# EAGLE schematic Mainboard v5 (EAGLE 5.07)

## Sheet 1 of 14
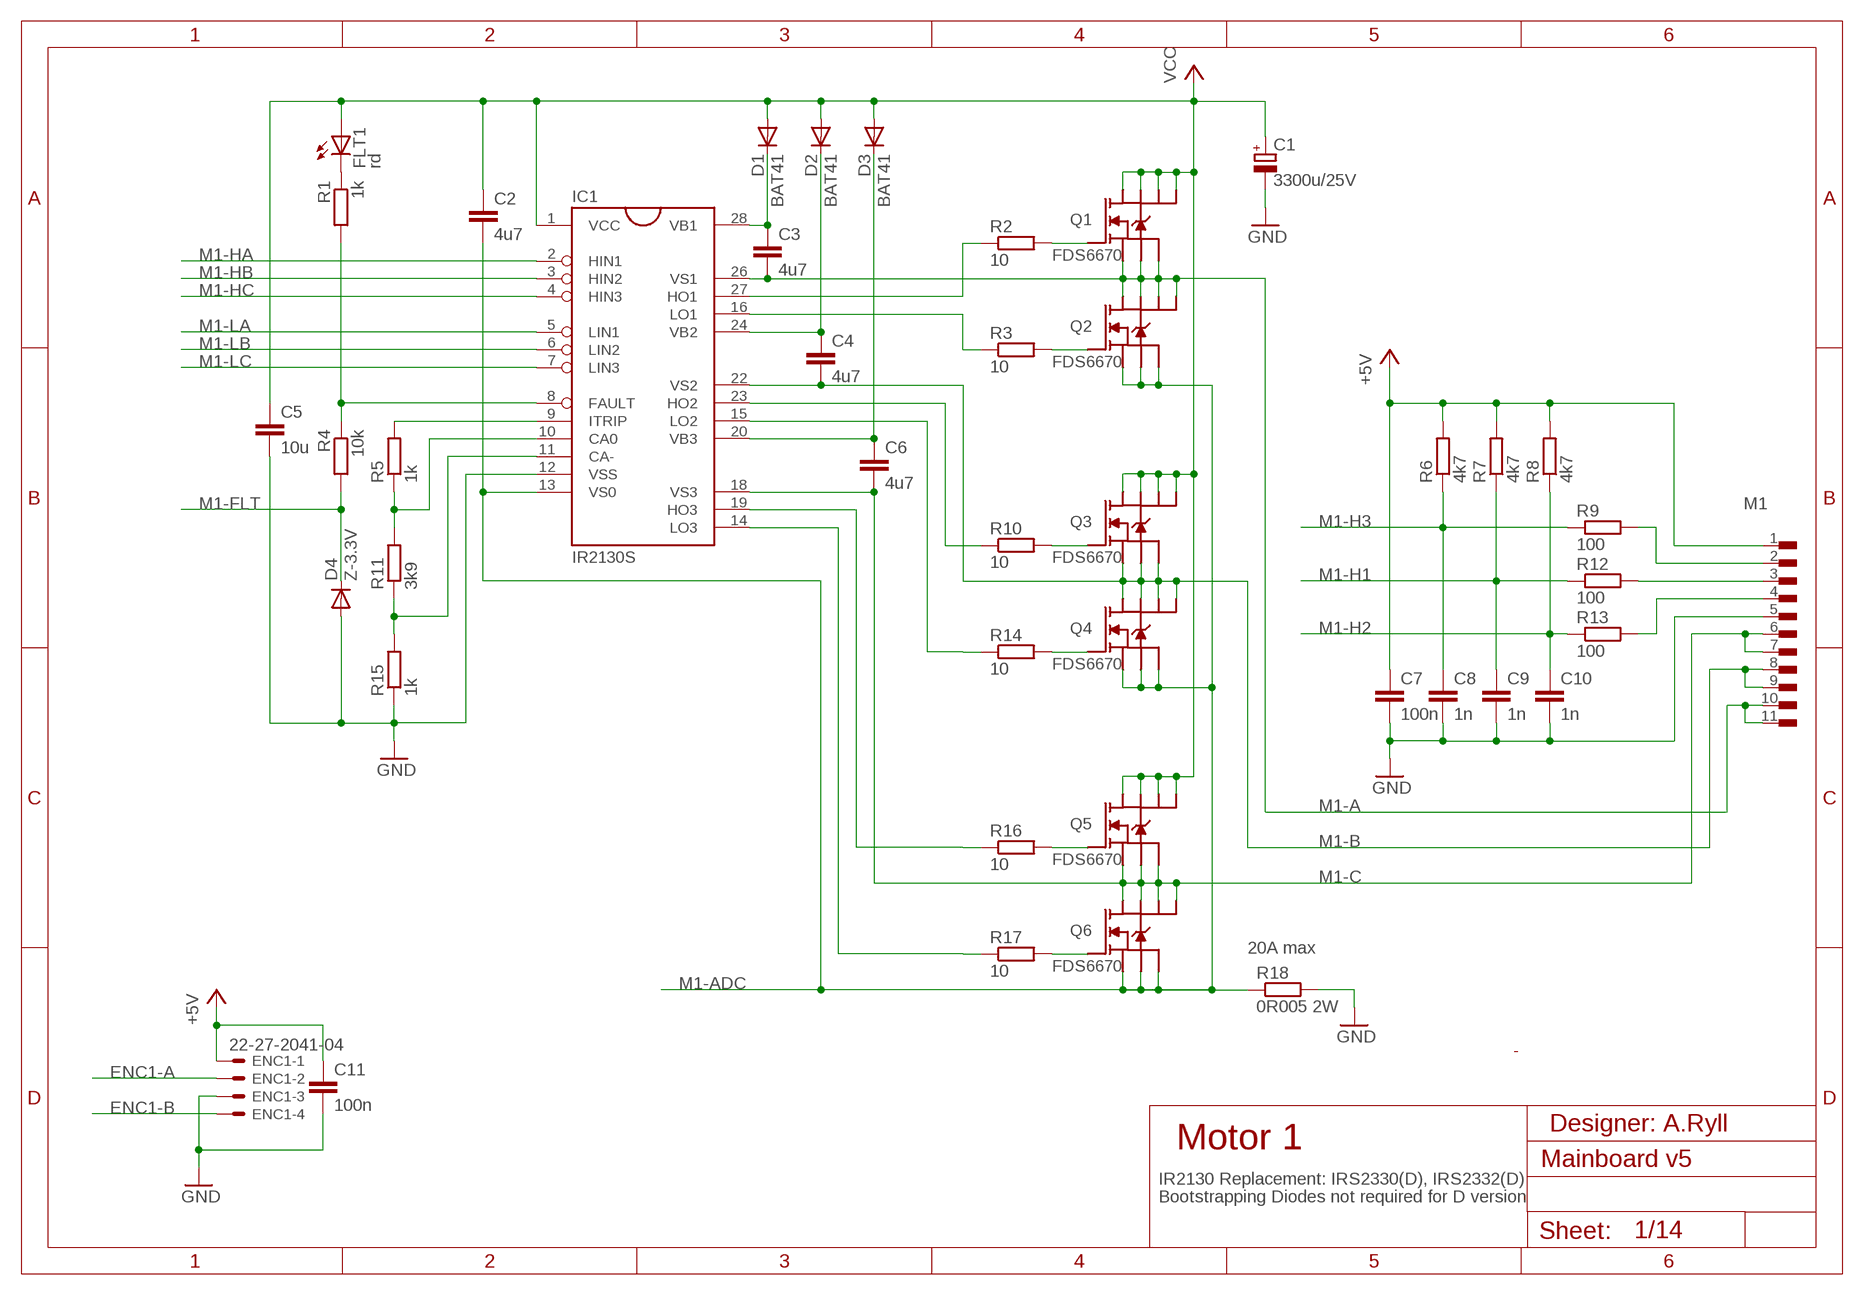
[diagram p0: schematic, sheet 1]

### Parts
C1  3300u/25V  CPOL-EU  [C25-16L]
C2  4u7  C-EUC0805  [C0805]
C3  4u7  C-EUC0805  [C0805]
C4  4u7  C-EUC0805  [C0805]
C5  10u  C-EUC0805  [C0805]
C6  4u7  C-EUC0805  [C0805]
C7  100n  C-EUC0805  [C0805]
C8  1n  C-EUC0805  [C0805]
C9  1n  C-EUC0805  [C0805]
C10  1n  C-EUC0805  [C0805]
C11  100n  C-EUC0805  [C0805]
D1  BAT41  DIODE-SOD323-W  [SOD323-W]
D2  BAT41  DIODE-SOD323-W  [SOD323-W]
D3  BAT41  DIODE-SOD323-W  [SOD323-W]
D4  Z-3.3V  DIODE-SOD323-W  [SOD323-W]
ENC1  22-27-2041-04  [6410-04]
FLT1  rd  LEDCHIP-LED0805  [CHIP-LED0805]
IC1  IR2130S  [SO28W]
M1  MOLEX11  [MOLEX11]
Q1  FDS6670  NMOS4D  [SOIC8]
Q2  FDS6670  NMOS4D  [SOIC8]
Q3  FDS6670  NMOS4D  [SOIC8]
Q4  FDS6670  NMOS4D  [SOIC8]
Q5  FDS6670  NMOS4D  [SOIC8]
Q6  FDS6670  NMOS4D  [SOIC8]
R1  1k  R-EU_R0805  [R0805]
R2  10  R-EU_R0805  [R0805]
R3  10  R-EU_R0805  [R0805]
R4  10k  R-EU_R0805  [R0805]
R5  1k  R-EU_R0805  [R0805]
R6  4k7  R-EU_R0805  [R0805]
R7  4k7  R-EU_R0805  [R0805]
R8  4k7  R-EU_R0805  [R0805]
R9  100  R-EU_R0805  [R0805]
R10  10  R-EU_R0805  [R0805]
R11  3k9  R-EU_R0805  [R0805]
R12  100  R-EU_R0805  [R0805]
R13  100  R-EU_R0805  [R0805]
R14  10  R-EU_R0805  [R0805]
R15  1k  R-EU_R0805  [R0805]
R16  10  R-EU_R0805  [R0805]
R17  10  R-EU_R0805  [R0805]
R18  0R005 2W  R-EU_R2512  [R2512]

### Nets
+5V: C7.1 C11.1 ENC1.1 M1.1(-1) R6.2 R7.2 R8.2 ; also sheet 2,3,4,5,8,12
ENC1-A: ENC1.2 ; also sheet 11
ENC1-B: ENC1.4 ; also sheet 11
FLT1: IC1.8(FAULT) R1.2 R4.1
GND: C1.B(-) C5.2 C7.2 C8.2 C9.2 C10.2 C11.2 D4.A ENC1.3 IC1.12(VSS) M1.5(-5) R15.1 R18.2 ; also sheet 2,3,4,5,6,7,8,9,10,11,12,13,14
M1-A: C3.2 IC1.26(VS1) M1.10(-10) M1.11(-11) Q1.1(S1) Q1.2(S2) Q1.3(S3) Q2.5(D1) Q2.6(D2) Q2.7(D3) Q2.8(D4)
M1-ADC: C2.2 IC1.13(VS0) Q2.1(S1) Q2.2(S2) Q2.3(S3) Q4.1(S1) Q4.2(S2) Q4.3(S3) Q6.1(S1) Q6.2(S2) Q6.3(S3) R18.1 ; also sheet 6
M1-B: C4.2 IC1.22(VS2) M1.8(-8) M1.9(-9) Q3.1(S1) Q3.2(S2) Q3.3(S3) Q4.5(D1) Q4.6(D2) Q4.7(D3) Q4.8(D4)
M1-C: C6.2 IC1.18(VS3) M1.6(-6) M1.7(-7) Q5.1(S1) Q5.2(S2) Q5.3(S3) Q6.5(D1) Q6.6(D2) Q6.7(D3) Q6.8(D4)
M1-FLT: D4.C R4.2 ; also sheet 7
M1-H1: C9.1 R7.1 R12.1 ; also sheet 8,11
M1-H2: C10.1 R8.1 R13.1 ; also sheet 8,11
M1-H3: C8.1 R6.1 R9.1 ; also sheet 8,11
M1-HA: IC1.2(HIN1) ; also sheet 11
M1-HB: IC1.3(HIN2) ; also sheet 11
M1-HC: IC1.4(HIN3) ; also sheet 11
M1-LA: IC1.5(LIN1) ; also sheet 11
M1-LB: IC1.6(LIN2) ; also sheet 11
M1-LC: IC1.7(LIN3) ; also sheet 11
N$1: IC1.9(ITRIP) R5.2
N$2: Q1.4(G) R2.2
N$3: IC1.27(HO1) R2.1
N$4: Q2.4(G) R3.2
N$5: IC1.23(HO2) R10.1
N$8: M1.2(-2) R9.2
N$9: M1.3(-3) R12.2
N$10: M1.4(-4) R13.2
N$11: Q3.4(G) R10.2
N$12: IC1.15(LO2) R14.1
N$13: Q4.4(G) R14.2
N$16: IC1.19(HO3) R16.1
N$17: Q5.4(G) R16.2
N$18: IC1.14(LO3) R17.1
N$19: Q6.4(G) R17.2
N$33: C3.1 D1.C IC1.28(VB1)
N$35: C4.1 D2.C IC1.24(VB2)
N$37: C6.1 D3.C IC1.20(VB3)
N$39: IC1.16(LO1) R3.1
N$46: IC1.11(CA-) R11.1 R15.2
N$51: FLT1.C R1.1
N$146: IC1.10(CA0) R5.1 R11.2
VCC: C1.A(+) C2.1 C5.1 D1.A D2.A D3.A FLT1.A IC1.1(VCC) Q1.5(D1) Q1.6(D2) Q1.7(D3) Q1.8(D4) Q3.5(D1) Q3.6(D2) Q3.7(D3) Q3.8(D4) Q5.5(D1) Q5.6(D2) Q5.7(D3) Q5.8(D4) ; also sheet 2,3,4,5,12

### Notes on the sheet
- 20A max
- Designer: A.Ryll
- Motor 1
- IR2130 Replacement: IRS2330(D), IRS2332(D)
- Bootstrapping Diodes not required for D version

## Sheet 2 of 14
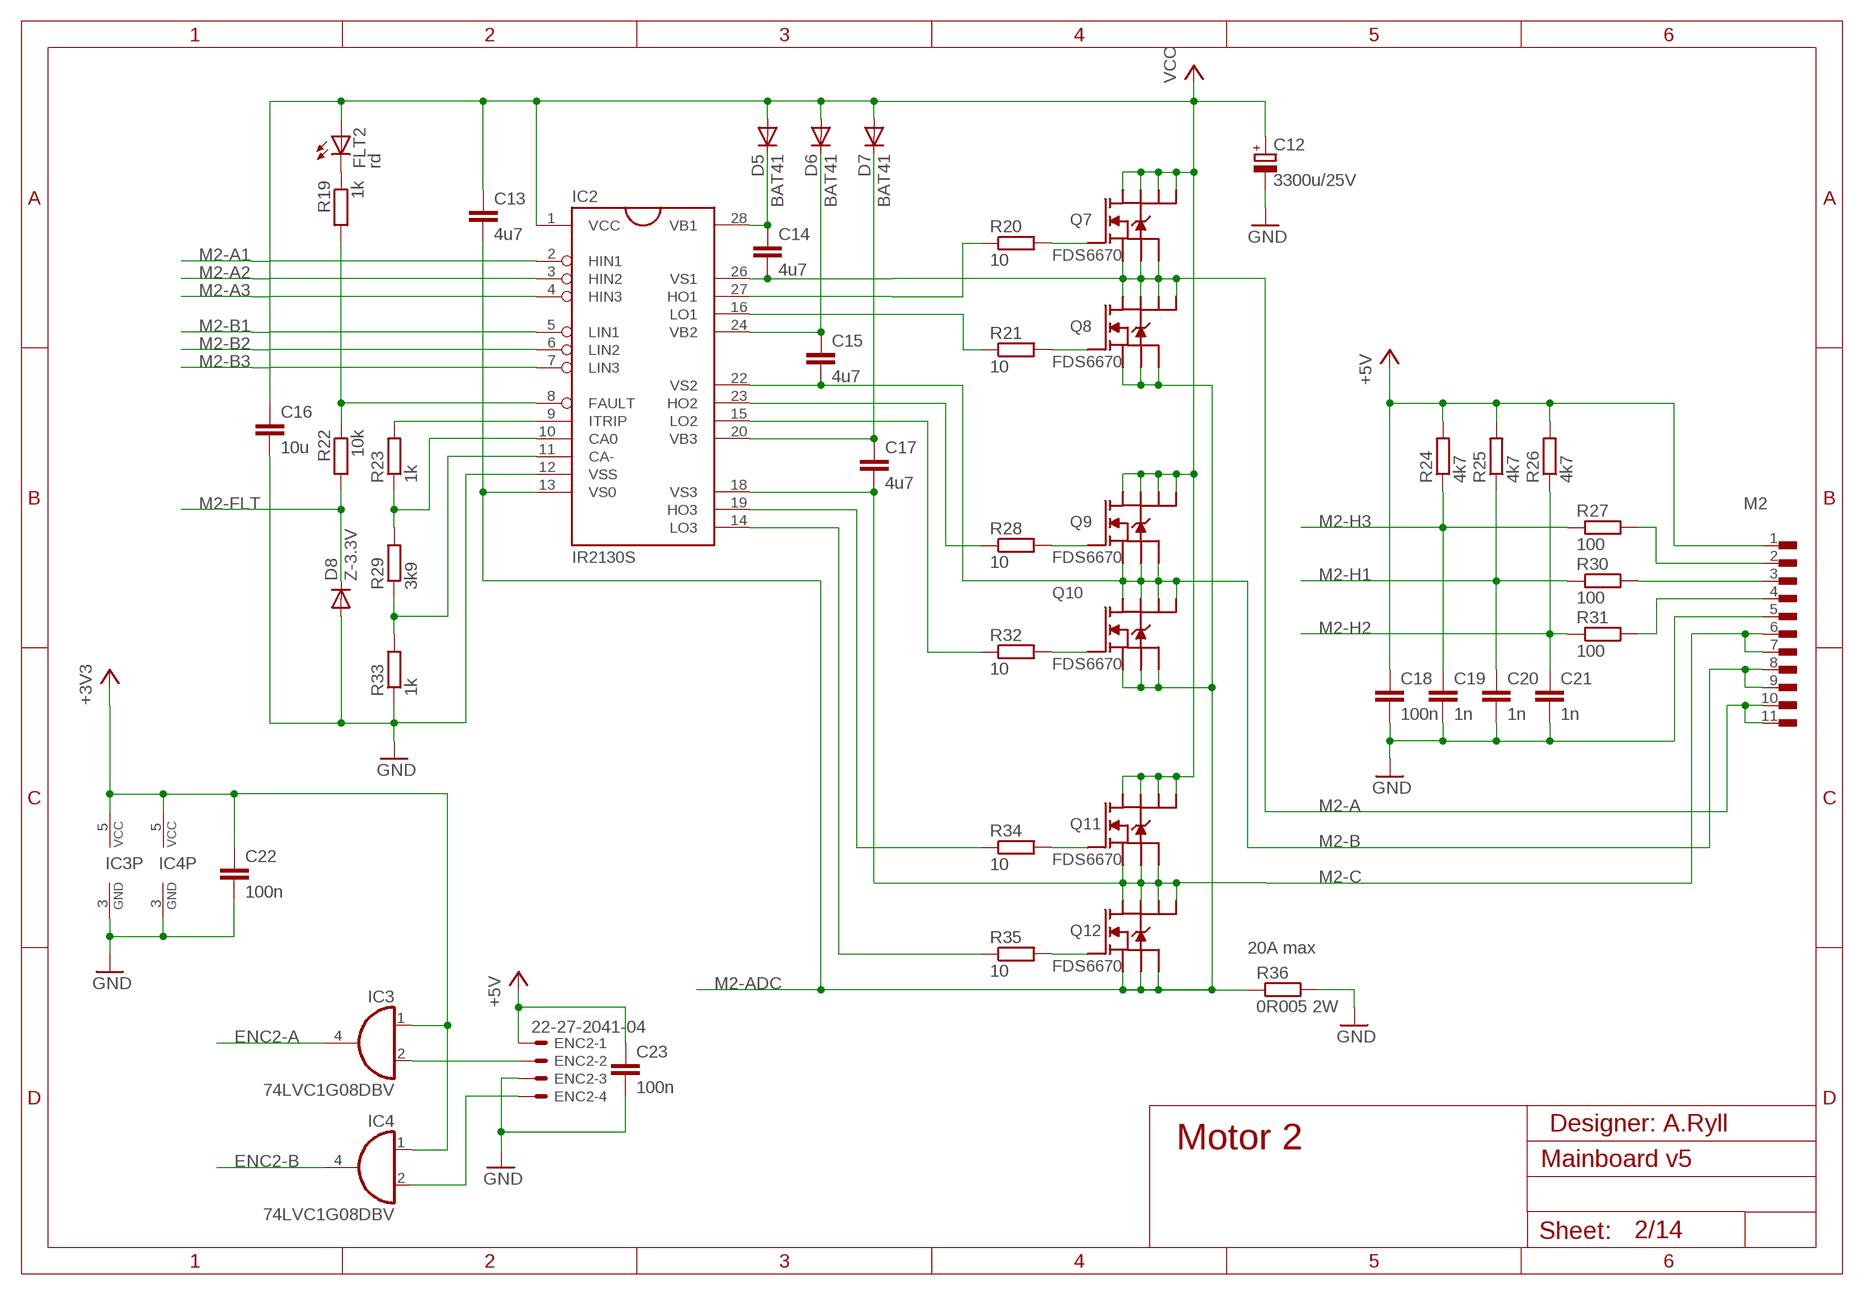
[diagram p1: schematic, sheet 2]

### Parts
C12  3300u/25V  CPOL-EU  [C25-16L]
C13  4u7  C-EUC0805  [C0805]
C14  4u7  C-EUC0805  [C0805]
C15  4u7  C-EUC0805  [C0805]
C16  10u  C-EUC0805  [C0805]
C17  4u7  C-EUC0805  [C0805]
C18  100n  C-EUC0805  [C0805]
C19  1n  C-EUC0805  [C0805]
C20  1n  C-EUC0805  [C0805]
C21  1n  C-EUC0805  [C0805]
C22  100n  C-EUC0805  [C0805]
C23  100n  C-EUC0805  [C0805]
D5  BAT41  DIODE-SOD323-W  [SOD323-W]
D6  BAT41  DIODE-SOD323-W  [SOD323-W]
D7  BAT41  DIODE-SOD323-W  [SOD323-W]
D8  Z-3.3V  DIODE-SOD323-W  [SOD323-W]
ENC2  22-27-2041-04  [6410-04]
FLT2  rd  LEDCHIP-LED0805  [CHIP-LED0805]
IC2  IR2130S  [SO28W]
IC3  74LVC1G08DBV  [SOT23-5]
IC4  74LVC1G08DBV  [SOT23-5]
M2  MOLEX11  [MOLEX11]
Q7  FDS6670  NMOS4D  [SOIC8]
Q8  FDS6670  NMOS4D  [SOIC8]
Q9  FDS6670  NMOS4D  [SOIC8]
Q10  FDS6670  NMOS4D  [SOIC8]
Q11  FDS6670  NMOS4D  [SOIC8]
Q12  FDS6670  NMOS4D  [SOIC8]
R19  1k  R-EU_R0805  [R0805]
R20  10  R-EU_R0805  [R0805]
R21  10  R-EU_R0805  [R0805]
R22  10k  R-EU_R0805  [R0805]
R23  1k  R-EU_R0805  [R0805]
R24  4k7  R-EU_R0805  [R0805]
R25  4k7  R-EU_R0805  [R0805]
R26  4k7  R-EU_R0805  [R0805]
R27  100  R-EU_R0805  [R0805]
R28  10  R-EU_R0805  [R0805]
R29  3k9  R-EU_R0805  [R0805]
R30  100  R-EU_R0805  [R0805]
R31  100  R-EU_R0805  [R0805]
R32  10  R-EU_R0805  [R0805]
R33  1k  R-EU_R0805  [R0805]
R34  10  R-EU_R0805  [R0805]
R35  10  R-EU_R0805  [R0805]
R36  0R005 2W  R-EU_R2512  [R2512]

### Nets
+3V3: C22.1 IC3.1(I0) IC3.5(VCC) IC4.1(I0) IC4.5(VCC) ; also sheet 6,7,8,9,10,11,12,13,14
+5V: C18.1 C23.1 ENC2.1 M2.1(-1) R24.2 R25.2 R26.2 ; also sheet 1,3,4,5,8,12
ENC2-A: IC3.4(O) ; also sheet 11
ENC2-B: IC4.4(O) ; also sheet 11
FLT2: IC2.8(FAULT) R19.2 R22.1
GND: C12.B(-) C16.2 C18.2 C19.2 C20.2 C21.2 C22.2 C23.2 D8.A ENC2.3 IC2.12(VSS) IC3.3(GND) IC4.3(GND) M2.5(-5) R33.1 R36.2 ; also sheet 1,3,4,5,6,7,8,9,10,11,12,13,14
M2-A: C14.2 IC2.26(VS1) M2.10(-10) M2.11(-11) Q7.1(S1) Q7.2(S2) Q7.3(S3) Q8.5(D1) Q8.6(D2) Q8.7(D3) Q8.8(D4)
M2-A1: IC2.2(HIN1) ; also sheet 11
M2-A2: IC2.3(HIN2) ; also sheet 11
M2-A3: IC2.4(HIN3) ; also sheet 11
M2-ADC: C13.2 IC2.13(VS0) Q8.1(S1) Q8.2(S2) Q8.3(S3) Q10.1(S1) Q10.2(S2) Q10.3(S3) Q12.1(S1) Q12.2(S2) Q12.3(S3) R36.1 ; also sheet 6
M2-B: C15.2 IC2.22(VS2) M2.8(-8) M2.9(-9) Q9.1(S1) Q9.2(S2) Q9.3(S3) Q10.5(D1) Q10.6(D2) Q10.7(D3) Q10.8(D4)
M2-B1: IC2.5(LIN1) ; also sheet 11
M2-B2: IC2.6(LIN2) ; also sheet 11
M2-B3: IC2.7(LIN3) ; also sheet 11
M2-C: C17.2 IC2.18(VS3) M2.6(-6) M2.7(-7) Q11.1(S1) Q11.2(S2) Q11.3(S3) Q12.5(D1) Q12.6(D2) Q12.7(D3) Q12.8(D4)
M2-FLT: D8.C R22.2 ; also sheet 7
M2-H1: C20.1 R25.1 R30.1 ; also sheet 8,11
M2-H2: C21.1 R26.1 R31.1 ; also sheet 8,11
M2-H3: C19.1 R24.1 R27.1 ; also sheet 8,11
N$34: IC2.23(HO2) R28.1
N$36: IC2.15(LO2) R32.1
N$38: IC2.19(HO3) R34.1
N$40: IC2.14(LO3) R35.1
N$41: C14.1 D5.C IC2.28(VB1)
N$42: C15.1 D6.C IC2.24(VB2)
N$43: C17.1 D7.C IC2.20(VB3)
N$44: IC2.16(LO1) R21.1
N$45: IC2.11(CA-) R29.1 R33.2
N$48: FLT2.C R19.1
N$49: IC2.27(HO1) R20.1
N$52: IC2.9(ITRIP) R23.2
N$76: ENC2.2 IC3.2(I1)
N$77: ENC2.4 IC4.2(I1)
N$100: Q7.4(G) R20.2
N$117: IC2.10(CA0) R23.1 R29.2
N$121: Q8.4(G) R21.2
N$124: M2.2(-2) R27.2
N$127: M2.4(-4) R31.2
N$148: M2.3(-3) R30.2
N$188: Q9.4(G) R28.2
N$189: Q10.4(G) R32.2
N$190: Q11.4(G) R34.2
N$191: Q12.4(G) R35.2
VCC: C12.A(+) C13.1 C16.1 D5.A D6.A D7.A FLT2.A IC2.1(VCC) Q7.5(D1) Q7.6(D2) Q7.7(D3) Q7.8(D4) Q9.5(D1) Q9.6(D2) Q9.7(D3) Q9.8(D4) Q11.5(D1) Q11.6(D2) Q11.7(D3) Q11.8(D4) ; also sheet 1,3,4,5,12

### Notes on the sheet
- 20A max
- Designer: A.Ryll
- Motor 2

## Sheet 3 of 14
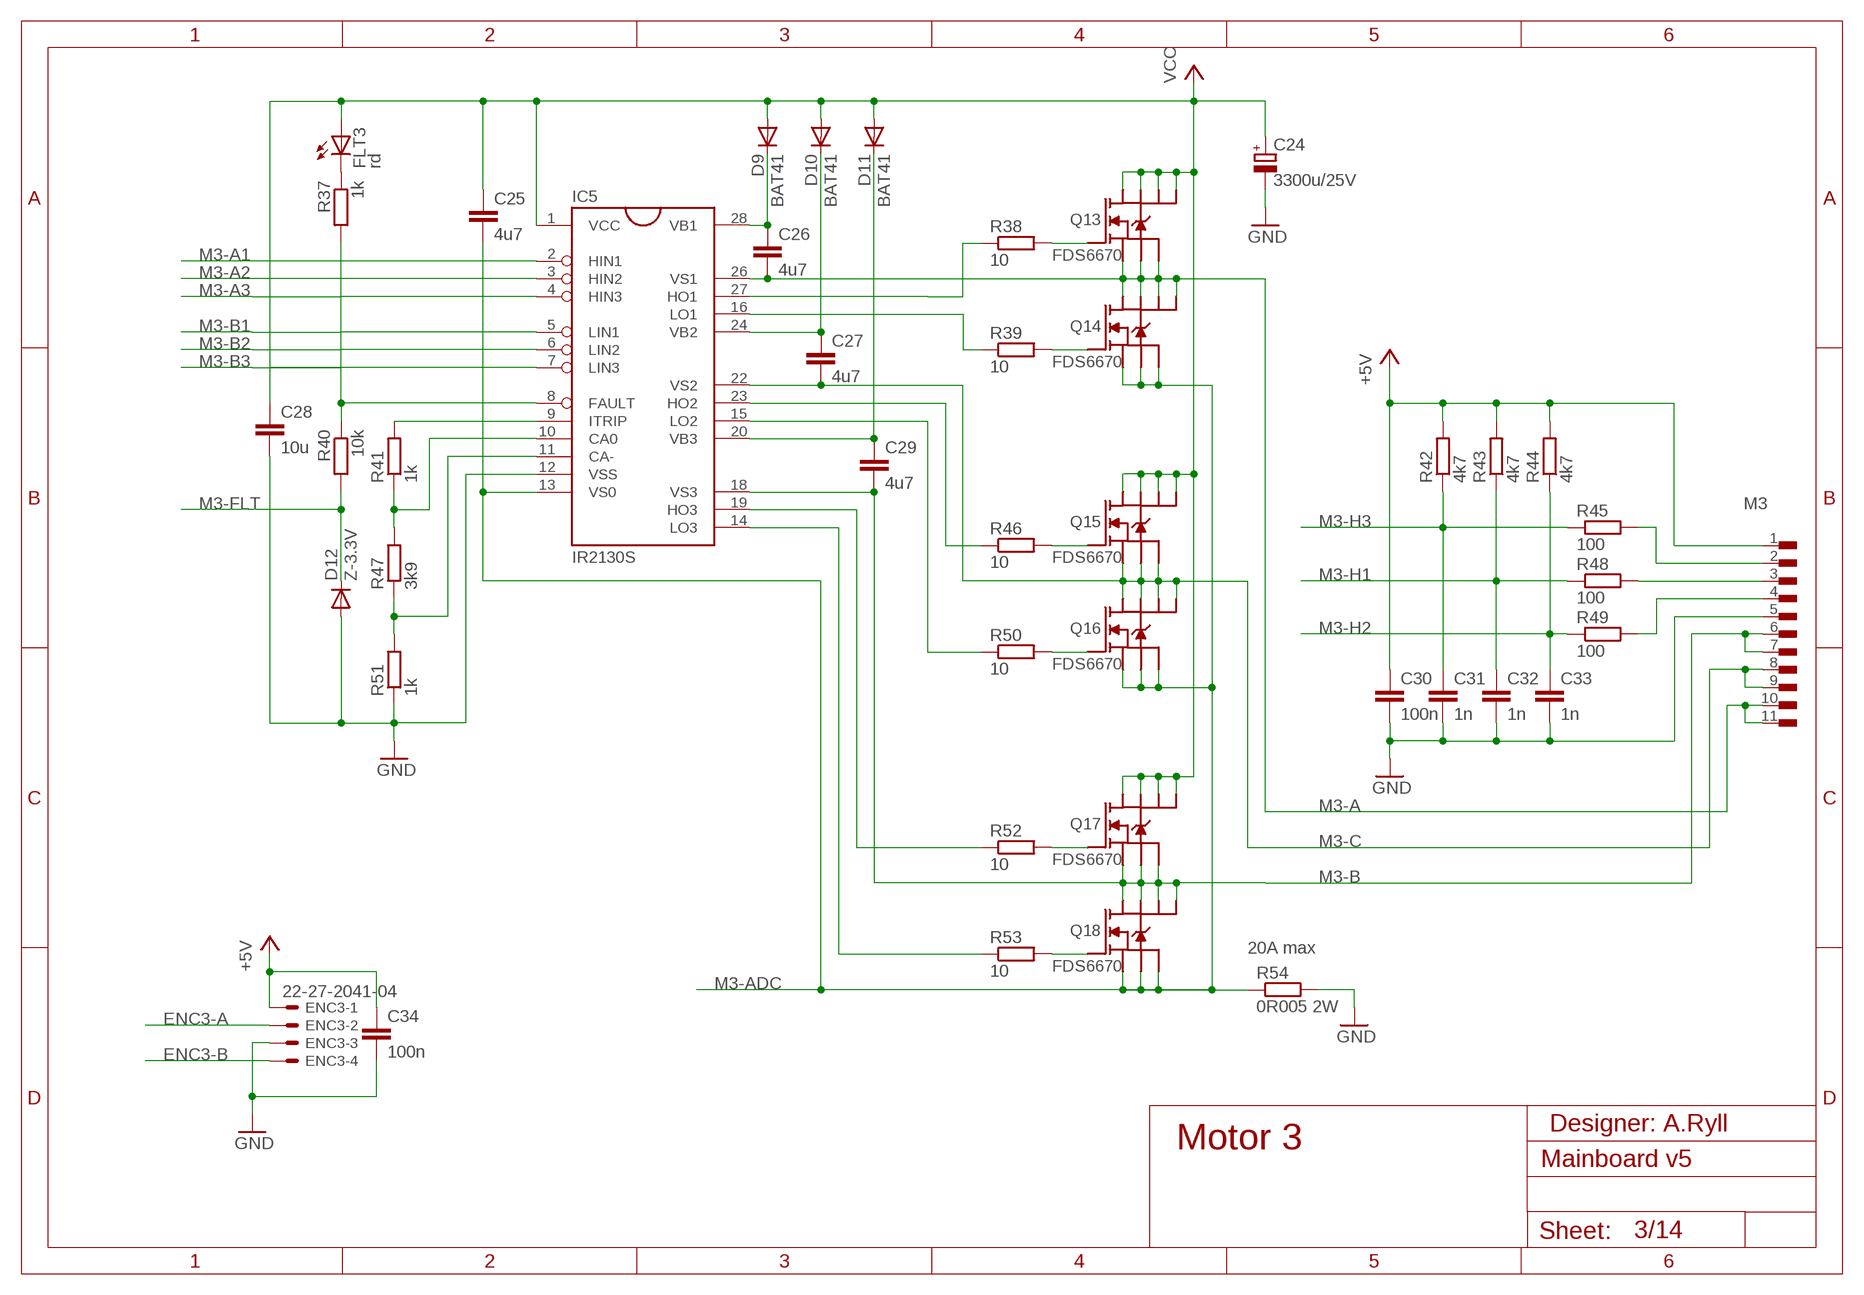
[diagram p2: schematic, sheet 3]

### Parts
C24  3300u/25V  CPOL-EU  [C25-16L]
C25  4u7  C-EUC0805  [C0805]
C26  4u7  C-EUC0805  [C0805]
C27  4u7  C-EUC0805  [C0805]
C28  10u  C-EUC0805  [C0805]
C29  4u7  C-EUC0805  [C0805]
C30  100n  C-EUC0805  [C0805]
C31  1n  C-EUC0805  [C0805]
C32  1n  C-EUC0805  [C0805]
C33  1n  C-EUC0805  [C0805]
C34  100n  C-EUC0805  [C0805]
D9  BAT41  DIODE-SOD323-W  [SOD323-W]
D10  BAT41  DIODE-SOD323-W  [SOD323-W]
D11  BAT41  DIODE-SOD323-W  [SOD323-W]
D12  Z-3.3V  DIODE-SOD323-W  [SOD323-W]
ENC3  22-27-2041-04  [6410-04]
FLT3  rd  LEDCHIP-LED0805  [CHIP-LED0805]
IC5  IR2130S  [SO28W]
M3  MOLEX11  [MOLEX11]
Q13  FDS6670  NMOS4D  [SOIC8]
Q14  FDS6670  NMOS4D  [SOIC8]
Q15  FDS6670  NMOS4D  [SOIC8]
Q16  FDS6670  NMOS4D  [SOIC8]
Q17  FDS6670  NMOS4D  [SOIC8]
Q18  FDS6670  NMOS4D  [SOIC8]
R37  1k  R-EU_R0805  [R0805]
R38  10  R-EU_R0805  [R0805]
R39  10  R-EU_R0805  [R0805]
R40  10k  R-EU_R0805  [R0805]
R41  1k  R-EU_R0805  [R0805]
R42  4k7  R-EU_R0805  [R0805]
R43  4k7  R-EU_R0805  [R0805]
R44  4k7  R-EU_R0805  [R0805]
R45  100  R-EU_R0805  [R0805]
R46  10  R-EU_R0805  [R0805]
R47  3k9  R-EU_R0805  [R0805]
R48  100  R-EU_R0805  [R0805]
R49  100  R-EU_R0805  [R0805]
R50  10  R-EU_R0805  [R0805]
R51  1k  R-EU_R0805  [R0805]
R52  10  R-EU_R0805  [R0805]
R53  10  R-EU_R0805  [R0805]
R54  0R005 2W  R-EU_R2512  [R2512]

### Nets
+5V: C30.1 C34.1 ENC3.1 M3.1(-1) R42.2 R43.2 R44.2 ; also sheet 1,2,4,5,8,12
ENC3-A: ENC3.2 ; also sheet 11
ENC3-B: ENC3.4 ; also sheet 11
FLT3: IC5.8(FAULT) R37.2 R40.1
GND: C24.B(-) C28.2 C30.2 C31.2 C32.2 C33.2 C34.2 D12.A ENC3.3 IC5.12(VSS) M3.5(-5) R51.1 R54.2 ; also sheet 1,2,4,5,6,7,8,9,10,11,12,13,14
M3-A: C26.2 IC5.26(VS1) M3.10(-10) M3.11(-11) Q13.1(S1) Q13.2(S2) Q13.3(S3) Q14.5(D1) Q14.6(D2) Q14.7(D3) Q14.8(D4)
M3-A1: IC5.2(HIN1) ; also sheet 11
M3-A2: IC5.3(HIN2) ; also sheet 11
M3-A3: IC5.4(HIN3) ; also sheet 11
M3-ADC: C25.2 IC5.13(VS0) Q14.1(S1) Q14.2(S2) Q14.3(S3) Q16.1(S1) Q16.2(S2) Q16.3(S3) Q18.1(S1) Q18.2(S2) Q18.3(S3) R54.1 ; also sheet 6
M3-B: C27.2 IC5.22(VS2) M3.8(-8) M3.9(-9) Q15.1(S1) Q15.2(S2) Q15.3(S3) Q16.5(D1) Q16.6(D2) Q16.7(D3) Q16.8(D4)
M3-B1: IC5.5(LIN1) ; also sheet 11
M3-B2: IC5.6(LIN2) ; also sheet 11
M3-B3: IC5.7(LIN3) ; also sheet 11
M3-C: C29.2 IC5.18(VS3) M3.6(-6) M3.7(-7) Q17.1(S1) Q17.2(S2) Q17.3(S3) Q18.5(D1) Q18.6(D2) Q18.7(D3) Q18.8(D4)
M3-FLT: D12.C R40.2 ; also sheet 7
M3-H1: C32.1 R43.1 R48.1 ; also sheet 8,11
M3-H2: C33.1 R44.1 R49.1 ; also sheet 8,11
M3-H3: C31.1 R42.1 R45.1 ; also sheet 8,11
N$53: IC5.23(HO2) R46.1
N$54: IC5.15(LO2) R50.1
N$55: IC5.19(HO3) R52.1
N$56: IC5.14(LO3) R53.1
N$57: C26.1 D9.C IC5.28(VB1)
N$58: C27.1 D10.C IC5.24(VB2)
N$59: C29.1 D11.C IC5.20(VB3)
N$60: IC5.16(LO1) R39.1
N$61: IC5.11(CA-) R47.1 R51.2
N$63: FLT3.C R37.1
N$64: IC5.27(HO1) R38.1
N$65: IC5.9(ITRIP) R41.2
N$128: IC5.10(CA0) R41.1 R47.2
N$213: Q13.4(G) R38.2
N$215: Q14.4(G) R39.2
N$216: M3.2(-2) R45.2
N$217: M3.4(-4) R49.2
N$222: M3.3(-3) R48.2
N$223: Q15.4(G) R46.2
N$224: Q16.4(G) R50.2
N$225: Q17.4(G) R52.2
N$226: Q18.4(G) R53.2
VCC: C24.A(+) C25.1 C28.1 D9.A D10.A D11.A FLT3.A IC5.1(VCC) Q13.5(D1) Q13.6(D2) Q13.7(D3) Q13.8(D4) Q15.5(D1) Q15.6(D2) Q15.7(D3) Q15.8(D4) Q17.5(D1) Q17.6(D2) Q17.7(D3) Q17.8(D4) ; also sheet 1,2,4,5,12

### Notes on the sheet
- 20A max
- Designer: A.Ryll
- Motor 3

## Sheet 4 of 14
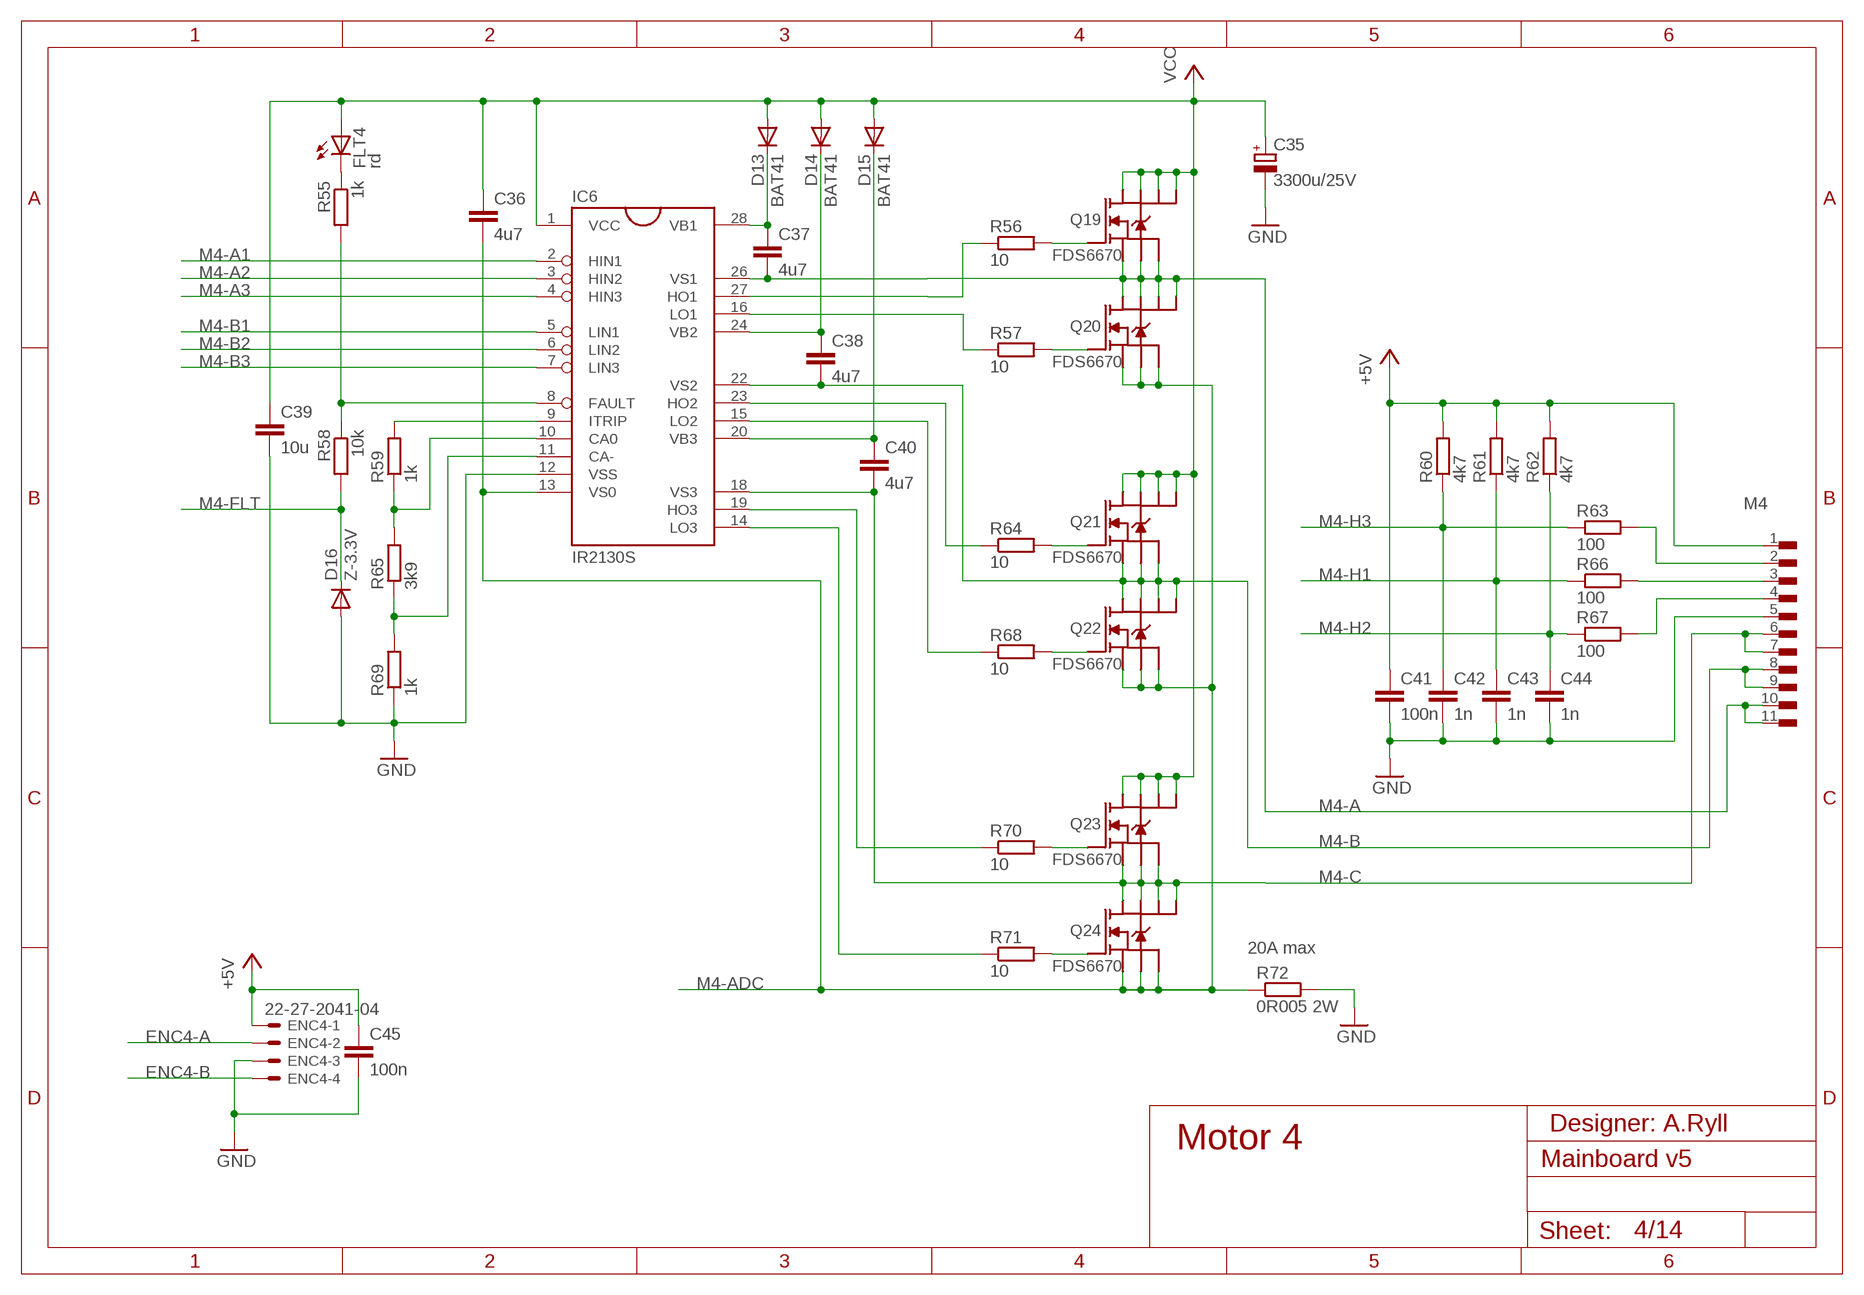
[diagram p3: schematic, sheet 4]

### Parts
C35  3300u/25V  CPOL-EUI  [C25-16L]
C36  4u7  C-EUC0805  [C0805]
C37  4u7  C-EUC0805  [C0805]
C38  4u7  C-EUC0805  [C0805]
C39  10u  C-EUC0805  [C0805]
C40  4u7  C-EUC0805  [C0805]
C41  100n  C-EUC0805  [C0805]
C42  1n  C-EUC0805  [C0805]
C43  1n  C-EUC0805  [C0805]
C44  1n  C-EUC0805  [C0805]
C45  100n  C-EUC0805  [C0805]
D13  BAT41  DIODE-SOD323-W  [SOD323-W]
D14  BAT41  DIODE-SOD323-W  [SOD323-W]
D15  BAT41  DIODE-SOD323-W  [SOD323-W]
D16  Z-3.3V  DIODE-SOD323-W  [SOD323-W]
ENC4  22-27-2041-04  [6410-04]
FLT4  rd  LEDCHIP-LED0805  [CHIP-LED0805]
IC6  IR2130S  [SO28W]
M4  MOLEX11  [MOLEX11]
Q19  FDS6670  NMOS4D  [SOIC8]
Q20  FDS6670  NMOS4D  [SOIC8]
Q21  FDS6670  NMOS4D  [SOIC8]
Q22  FDS6670  NMOS4D  [SOIC8]
Q23  FDS6670  NMOS4D  [SOIC8]
Q24  FDS6670  NMOS4D  [SOIC8]
R55  1k  R-EU_R0805  [R0805]
R56  10  R-EU_R0805  [R0805]
R57  10  R-EU_R0805  [R0805]
R58  10k  R-EU_R0805  [R0805]
R59  1k  R-EU_R0805  [R0805]
R60  4k7  R-EU_R0805  [R0805]
R61  4k7  R-EU_R0805  [R0805]
R62  4k7  R-EU_R0805  [R0805]
R63  100  R-EU_R0805  [R0805]
R64  10  R-EU_R0805  [R0805]
R65  3k9  R-EU_R0805  [R0805]
R66  100  R-EU_R0805  [R0805]
R67  100  R-EU_R0805  [R0805]
R68  10  R-EU_R0805  [R0805]
R69  1k  R-EU_R0805  [R0805]
R70  10  R-EU_R0805  [R0805]
R71  10  R-EU_R0805  [R0805]
R72  0R005 2W  R-EU_R2512  [R2512]

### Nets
+5V: C41.1 C45.1 ENC4.1 M4.1(-1) R60.2 R61.2 R62.2 ; also sheet 1,2,3,5,8,12
ENC4-A: ENC4.2 ; also sheet 11
ENC4-B: ENC4.4 ; also sheet 11
FLT4: IC6.8(FAULT) R55.2 R58.1
GND: C35.A(-) C39.2 C41.2 C42.2 C43.2 C44.2 C45.2 D16.A ENC4.3 IC6.12(VSS) M4.5(-5) R69.1 R72.2 ; also sheet 1,2,3,5,6,7,8,9,10,11,12,13,14
M4-A: C37.2 IC6.26(VS1) M4.10(-10) M4.11(-11) Q19.1(S1) Q19.2(S2) Q19.3(S3) Q20.5(D1) Q20.6(D2) Q20.7(D3) Q20.8(D4)
M4-A1: IC6.2(HIN1) ; also sheet 11
M4-A2: IC6.3(HIN2) ; also sheet 11
M4-A3: IC6.4(HIN3) ; also sheet 11
M4-ADC: C36.2 IC6.13(VS0) Q20.1(S1) Q20.2(S2) Q20.3(S3) Q22.1(S1) Q22.2(S2) Q22.3(S3) Q24.1(S1) Q24.2(S2) Q24.3(S3) R72.1 ; also sheet 6
M4-B: C38.2 IC6.22(VS2) M4.8(-8) M4.9(-9) Q21.1(S1) Q21.2(S2) Q21.3(S3) Q22.5(D1) Q22.6(D2) Q22.7(D3) Q22.8(D4)
M4-B1: IC6.5(LIN1) ; also sheet 11
M4-B2: IC6.6(LIN2) ; also sheet 11
M4-B3: IC6.7(LIN3) ; also sheet 11
M4-C: C40.2 IC6.18(VS3) M4.6(-6) M4.7(-7) Q23.1(S1) Q23.2(S2) Q23.3(S3) Q24.5(D1) Q24.6(D2) Q24.7(D3) Q24.8(D4)
M4-FLT: D16.C R58.2 ; also sheet 7
M4-H1: C43.1 R61.1 R66.1 ; also sheet 8,11
M4-H2: C44.1 R62.1 R67.1 ; also sheet 8,11
M4-H3: C42.1 R60.1 R63.1 ; also sheet 8,11
N$66: IC6.23(HO2) R64.1
N$67: IC6.15(LO2) R68.1
N$68: IC6.19(HO3) R70.1
N$69: IC6.14(LO3) R71.1
N$70: C37.1 D13.C IC6.28(VB1)
N$71: C38.1 D14.C IC6.24(VB2)
N$72: C40.1 D15.C IC6.20(VB3)
N$73: IC6.16(LO1) R57.1
N$74: IC6.11(CA-) R65.1 R69.2
N$80: FLT4.C R55.1
N$83: IC6.27(HO1) R56.1
N$86: IC6.9(ITRIP) R59.2
N$129: IC6.10(CA0) R59.1 R65.2
N$234: Q19.4(G) R56.2
N$236: Q20.4(G) R57.2
N$237: M4.2(-2) R63.2
N$238: M4.4(-4) R67.2
N$243: M4.3(-3) R66.2
N$244: Q21.4(G) R64.2
N$245: Q22.4(G) R68.2
N$246: Q23.4(G) R70.2
N$247: Q24.4(G) R71.2
VCC: C35.B(+) C36.1 C39.1 D13.A D14.A D15.A FLT4.A IC6.1(VCC) Q19.5(D1) Q19.6(D2) Q19.7(D3) Q19.8(D4) Q21.5(D1) Q21.6(D2) Q21.7(D3) Q21.8(D4) Q23.5(D1) Q23.6(D2) Q23.7(D3) Q23.8(D4) ; also sheet 1,2,3,5,12

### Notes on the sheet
- 20A max
- Designer: A.Ryll
- Motor 4

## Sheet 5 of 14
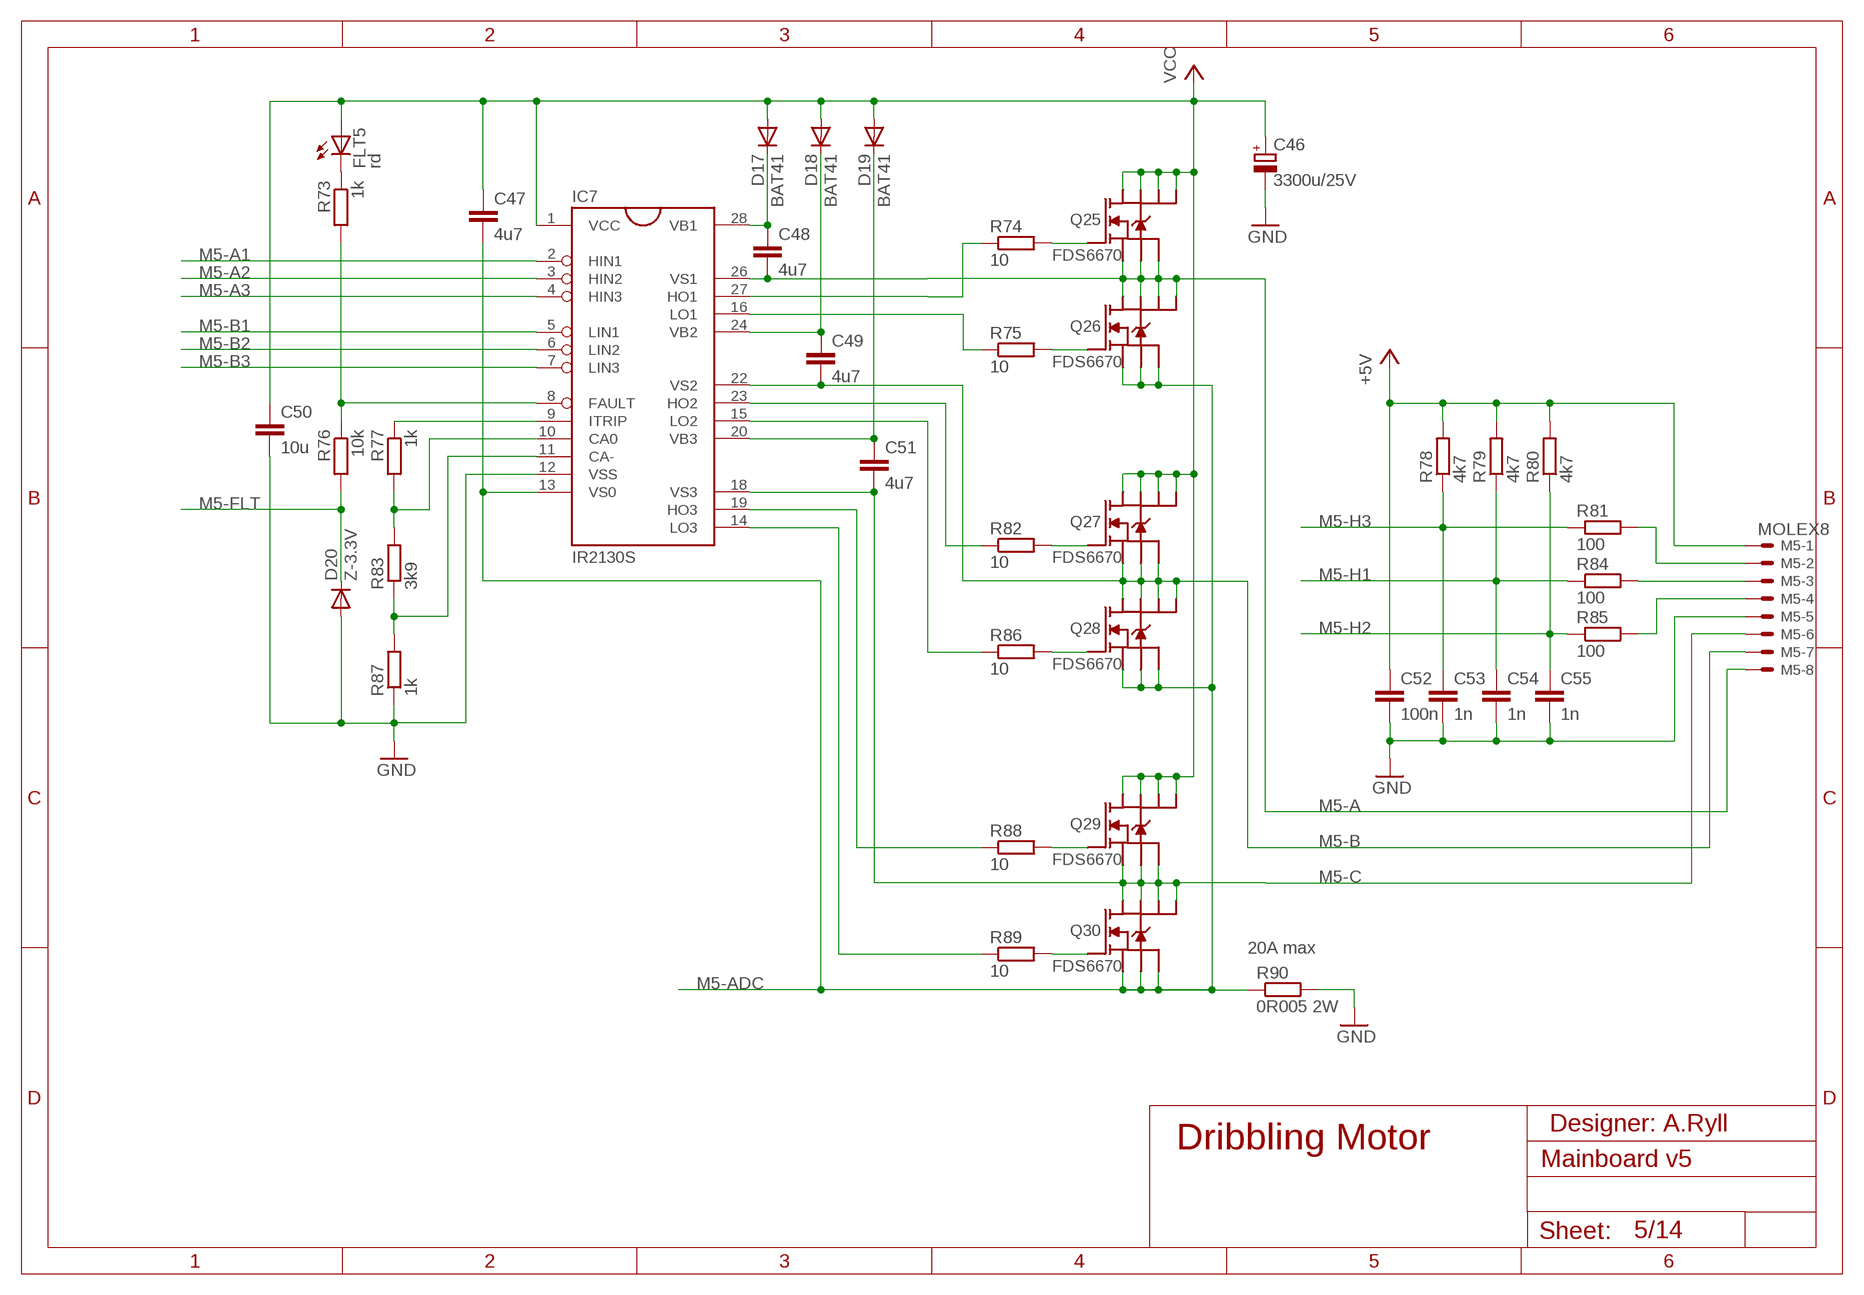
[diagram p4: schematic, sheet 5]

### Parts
C46  3300u/25V  CPOL-EUI  [C25-16L]
C47  4u7  C-EUC0805  [C0805]
C48  4u7  C-EUC0805  [C0805]
C49  4u7  C-EUC0805  [C0805]
C50  10u  C-EUC0805  [C0805]
C51  4u7  C-EUC0805  [C0805]
C52  100n  C-EUC0805  [C0805]
C53  1n  C-EUC0805  [C0805]
C54  1n  C-EUC0805  [C0805]
C55  1n  C-EUC0805  [C0805]
D17  BAT41  DIODE-SOD323-W  [SOD323-W]
D18  BAT41  DIODE-SOD323-W  [SOD323-W]
D19  BAT41  DIODE-SOD323-W  [SOD323-W]
D20  Z-3.3V  DIODE-SOD323-W  [SOD323-W]
FLT5  rd  LEDCHIP-LED0805  [CHIP-LED0805]
IC7  IR2130S  [SO28W]
M5  MOLEX8  22-27-2081-08  [6410-08]
Q25  FDS6670  NMOS4D  [SOIC8]
Q26  FDS6670  NMOS4D  [SOIC8]
Q27  FDS6670  NMOS4D  [SOIC8]
Q28  FDS6670  NMOS4D  [SOIC8]
Q29  FDS6670  NMOS4D  [SOIC8]
Q30  FDS6670  NMOS4D  [SOIC8]
R73  1k  R-EU_R0805  [R0805]
R74  10  R-EU_R0805  [R0805]
R75  10  R-EU_R0805  [R0805]
R76  10k  R-EU_R0805  [R0805]
R77  1k  R-EU_R0805  [R0805]
R78  4k7  R-EU_R0805  [R0805]
R79  4k7  R-EU_R0805  [R0805]
R80  4k7  R-EU_R0805  [R0805]
R81  100  R-EU_R0805  [R0805]
R82  10  R-EU_R0805  [R0805]
R83  3k9  R-EU_R0805  [R0805]
R84  100  R-EU_R0805  [R0805]
R85  100  R-EU_R0805  [R0805]
R86  10  R-EU_R0805  [R0805]
R87  1k  R-EU_R0805  [R0805]
R88  10  R-EU_R0805  [R0805]
R89  10  R-EU_R0805  [R0805]
R90  0R005 2W  R-EU_R2512  [R2512]

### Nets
+5V: C52.1 M5.1 R78.2 R79.2 R80.2 ; also sheet 1,2,3,4,8,12
FLT5: IC7.8(FAULT) R73.2 R76.1
GND: C46.A(-) C50.2 C52.2 C53.2 C54.2 C55.2 D20.A IC7.12(VSS) M5.5 R87.1 R90.2 ; also sheet 1,2,3,4,6,7,8,9,10,11,12,13,14
M5-A: C48.2 IC7.26(VS1) M5.8 Q25.1(S1) Q25.2(S2) Q25.3(S3) Q26.5(D1) Q26.6(D2) Q26.7(D3) Q26.8(D4)
M5-A1: IC7.2(HIN1) ; also sheet 11
M5-A2: IC7.3(HIN2) ; also sheet 11
M5-A3: IC7.4(HIN3) ; also sheet 11
M5-ADC: C47.2 IC7.13(VS0) Q26.1(S1) Q26.2(S2) Q26.3(S3) Q28.1(S1) Q28.2(S2) Q28.3(S3) Q30.1(S1) Q30.2(S2) Q30.3(S3) R90.1 ; also sheet 6
M5-B: C49.2 IC7.22(VS2) M5.7 Q27.1(S1) Q27.2(S2) Q27.3(S3) Q28.5(D1) Q28.6(D2) Q28.7(D3) Q28.8(D4)
M5-B1: IC7.5(LIN1) ; also sheet 11
M5-B2: IC7.6(LIN2) ; also sheet 11
M5-B3: IC7.7(LIN3) ; also sheet 11
M5-C: C51.2 IC7.18(VS3) M5.6 Q29.1(S1) Q29.2(S2) Q29.3(S3) Q30.5(D1) Q30.6(D2) Q30.7(D3) Q30.8(D4)
M5-FLT: D20.C R76.2 ; also sheet 7
M5-H1: C54.1 R79.1 R84.1 ; also sheet 8,11
M5-H2: C55.1 R80.1 R85.1 ; also sheet 8,11
M5-H3: C53.1 R78.1 R81.1 ; also sheet 8,11
N$89: IC7.23(HO2) R82.1
N$92: IC7.15(LO2) R86.1
N$93: IC7.19(HO3) R88.1
N$95: IC7.14(LO3) R89.1
N$96: C48.1 D17.C IC7.28(VB1)
N$97: C49.1 D18.C IC7.24(VB2)
N$99: C51.1 D19.C IC7.20(VB3)
N$145: IC7.10(CA0) R77.2 R83.2
N$147: IC7.16(LO1) R75.1
N$154: IC7.11(CA-) R83.1 R87.2
N$158: FLT5.C R73.1
N$162: IC7.27(HO1) R74.1
N$163: IC7.9(ITRIP) R77.1
N$255: Q25.4(G) R74.2
N$257: Q26.4(G) R75.2
N$258: M5.2 R81.2
N$259: M5.4 R85.2
N$264: M5.3 R84.2
N$265: Q27.4(G) R82.2
N$266: Q28.4(G) R86.2
N$267: Q29.4(G) R88.2
N$268: Q30.4(G) R89.2
VCC: C46.B(+) C47.1 C50.1 D17.A D18.A D19.A FLT5.A IC7.1(VCC) Q25.5(D1) Q25.6(D2) Q25.7(D3) Q25.8(D4) Q27.5(D1) Q27.6(D2) Q27.7(D3) Q27.8(D4) Q29.5(D1) Q29.6(D2) Q29.7(D3) Q29.8(D4) ; also sheet 1,2,3,4,12

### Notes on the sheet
- 20A max
- Designer: A.Ryll
- Dribbling Motor

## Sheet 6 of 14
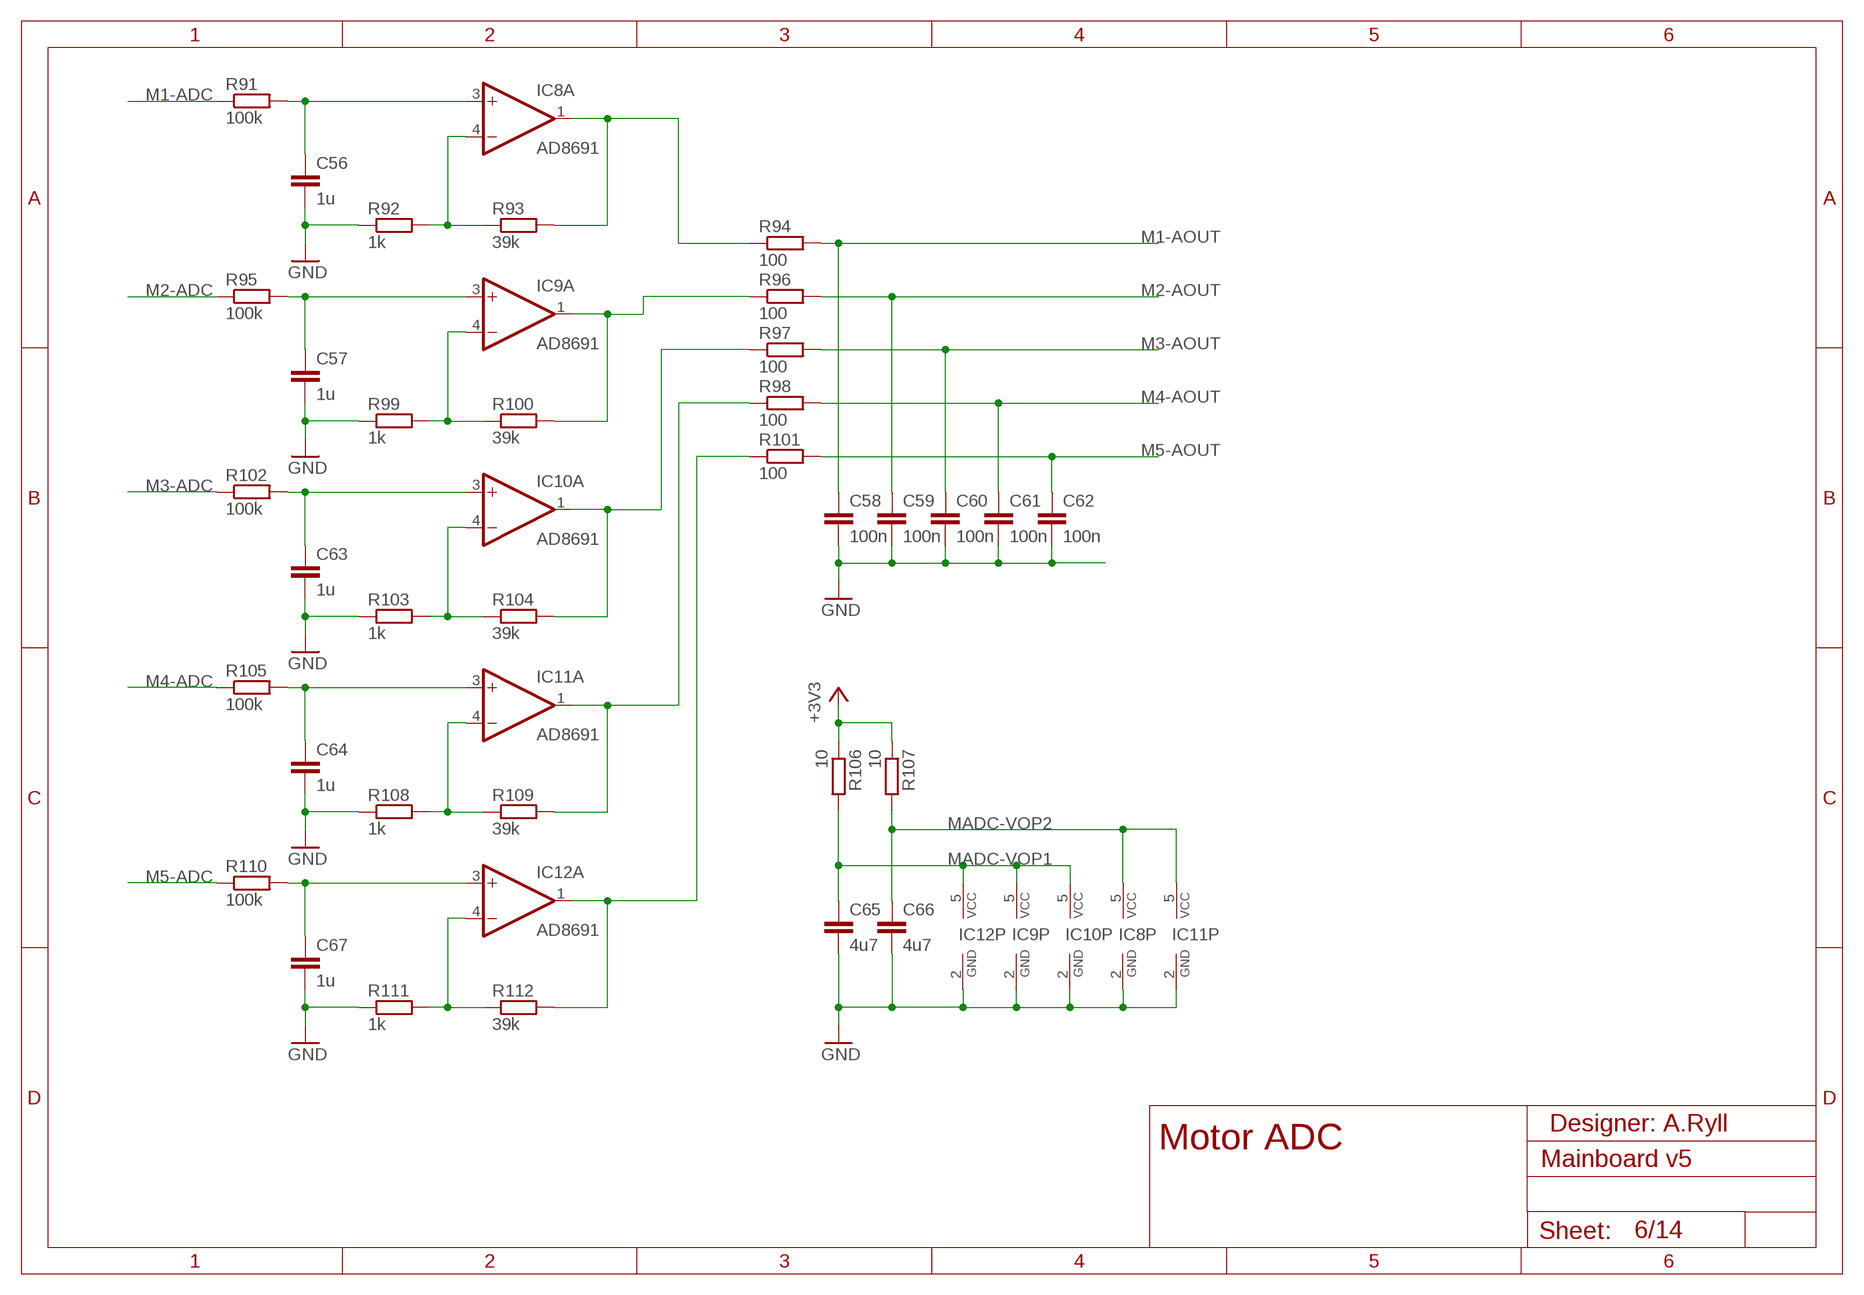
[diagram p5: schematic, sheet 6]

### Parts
C56  1u  C-EUC0805  [C0805]
C57  1u  C-EUC0805  [C0805]
C58  100n  C-EUC0805  [C0805]
C59  100n  C-EUC0805  [C0805]
C60  100n  C-EUC0805  [C0805]
C61  100n  C-EUC0805  [C0805]
C62  100n  C-EUC0805  [C0805]
C63  1u  C-EUC0805  [C0805]
C64  1u  C-EUC0805  [C0805]
C65  4u7  C-EUC0805  [C0805]
C66  4u7  C-EUC0805  [C0805]
C67  1u  C-EUC0805  [C0805]
IC8  AD8691  AD-OP1RT  [SOT23-5]
IC9  AD8691  AD-OP1RT  [SOT23-5]
IC10  AD8691  AD-OP1RT  [SOT23-5]
IC11  AD8691  AD-OP1RT  [SOT23-5]
IC12  AD8691  AD-OP1RT  [SOT23-5]
R91  100k  R-EU_R0805  [R0805]
R92  1k  R-EU_R0805  [R0805]
R93  39k  R-EU_R0805  [R0805]
R94  100  R-EU_R0805  [R0805]
R95  100k  R-EU_R0805  [R0805]
R96  100  R-EU_R0805  [R0805]
R97  100  R-EU_R0805  [R0805]
R98  100  R-EU_R0805  [R0805]
R99  1k  R-EU_R0805  [R0805]
R100  39k  R-EU_R0805  [R0805]
R101  100  R-EU_R0805  [R0805]
R102  100k  R-EU_R0805  [R0805]
R103  1k  R-EU_R0805  [R0805]
R104  39k  R-EU_R0805  [R0805]
R105  100k  R-EU_R0805  [R0805]
R106  10  R-EU_R0805  [R0805]
R107  10  R-EU_R0805  [R0805]
R108  1k  R-EU_R0805  [R0805]
R109  39k  R-EU_R0805  [R0805]
R110  100k  R-EU_R0805  [R0805]
R111  1k  R-EU_R0805  [R0805]
R112  39k  R-EU_R0805  [R0805]

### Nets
+3V3: R106.1 R107.1 ; also sheet 2,7,8,9,10,11,12,13,14
GND: C56.2 C57.2 C58.2 C59.2 C60.2 C61.2 C62.2 C63.2 C64.2 C65.2 C66.2 C67.2 IC8.2(P:GND) IC9.2(P:GND) IC10.2(P:GND) IC11.2(P:GND) IC12.2(P:GND) R92.1 R99.1 R103.1 R108.1 R111.1 ; also sheet 1,2,3,4,5,7,8,9,10,11,12,13,14
M1-ADC: R91.1 ; also sheet 1
M1-AOUT: C58.1 R94.2 ; also sheet 7
M2-ADC: R95.1 ; also sheet 2
M2-AOUT: C59.1 R96.2 ; also sheet 7
M3-ADC: R102.1 ; also sheet 3
M3-AOUT: C60.1 R97.2 ; also sheet 7
M4-ADC: R105.1 ; also sheet 4
M4-AOUT: C61.1 R98.2 ; also sheet 7
M5-ADC: R110.1 ; also sheet 5
M5-AOUT: C62.1 R101.2 ; also sheet 7
MADC-VOP1: C65.1 IC9.5(P:VCC) IC10.5(P:VCC) IC12.5(P:VCC) R106.2
MADC-VOP2: C66.1 IC8.5(P:VCC) IC11.5(P:VCC) R107.2
N$130: C56.1 IC8.3(A:+IN) R91.2
N$131: IC8.4(A:-IN) R92.2 R93.1
N$132: IC8.1(A:OUT) R93.2 R94.1
N$133: C57.1 IC9.3(A:+IN) R95.2
N$134: IC9.4(A:-IN) R99.2 R100.1
N$135: IC9.1(A:OUT) R96.1 R100.2
N$136: C63.1 IC10.3(A:+IN) R102.2
N$137: IC10.4(A:-IN) R103.2 R104.1
N$138: IC10.1(A:OUT) R97.1 R104.2
N$139: C64.1 IC11.3(A:+IN) R105.2
N$140: IC11.4(A:-IN) R108.2 R109.1
N$141: IC11.1(A:OUT) R98.1 R109.2
N$142: C67.1 IC12.3(A:+IN) R110.2
N$143: IC12.4(A:-IN) R111.2 R112.1
N$144: IC12.1(A:OUT) R101.1 R112.2

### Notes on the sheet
- Designer: A.Ryll
- Motor ADC

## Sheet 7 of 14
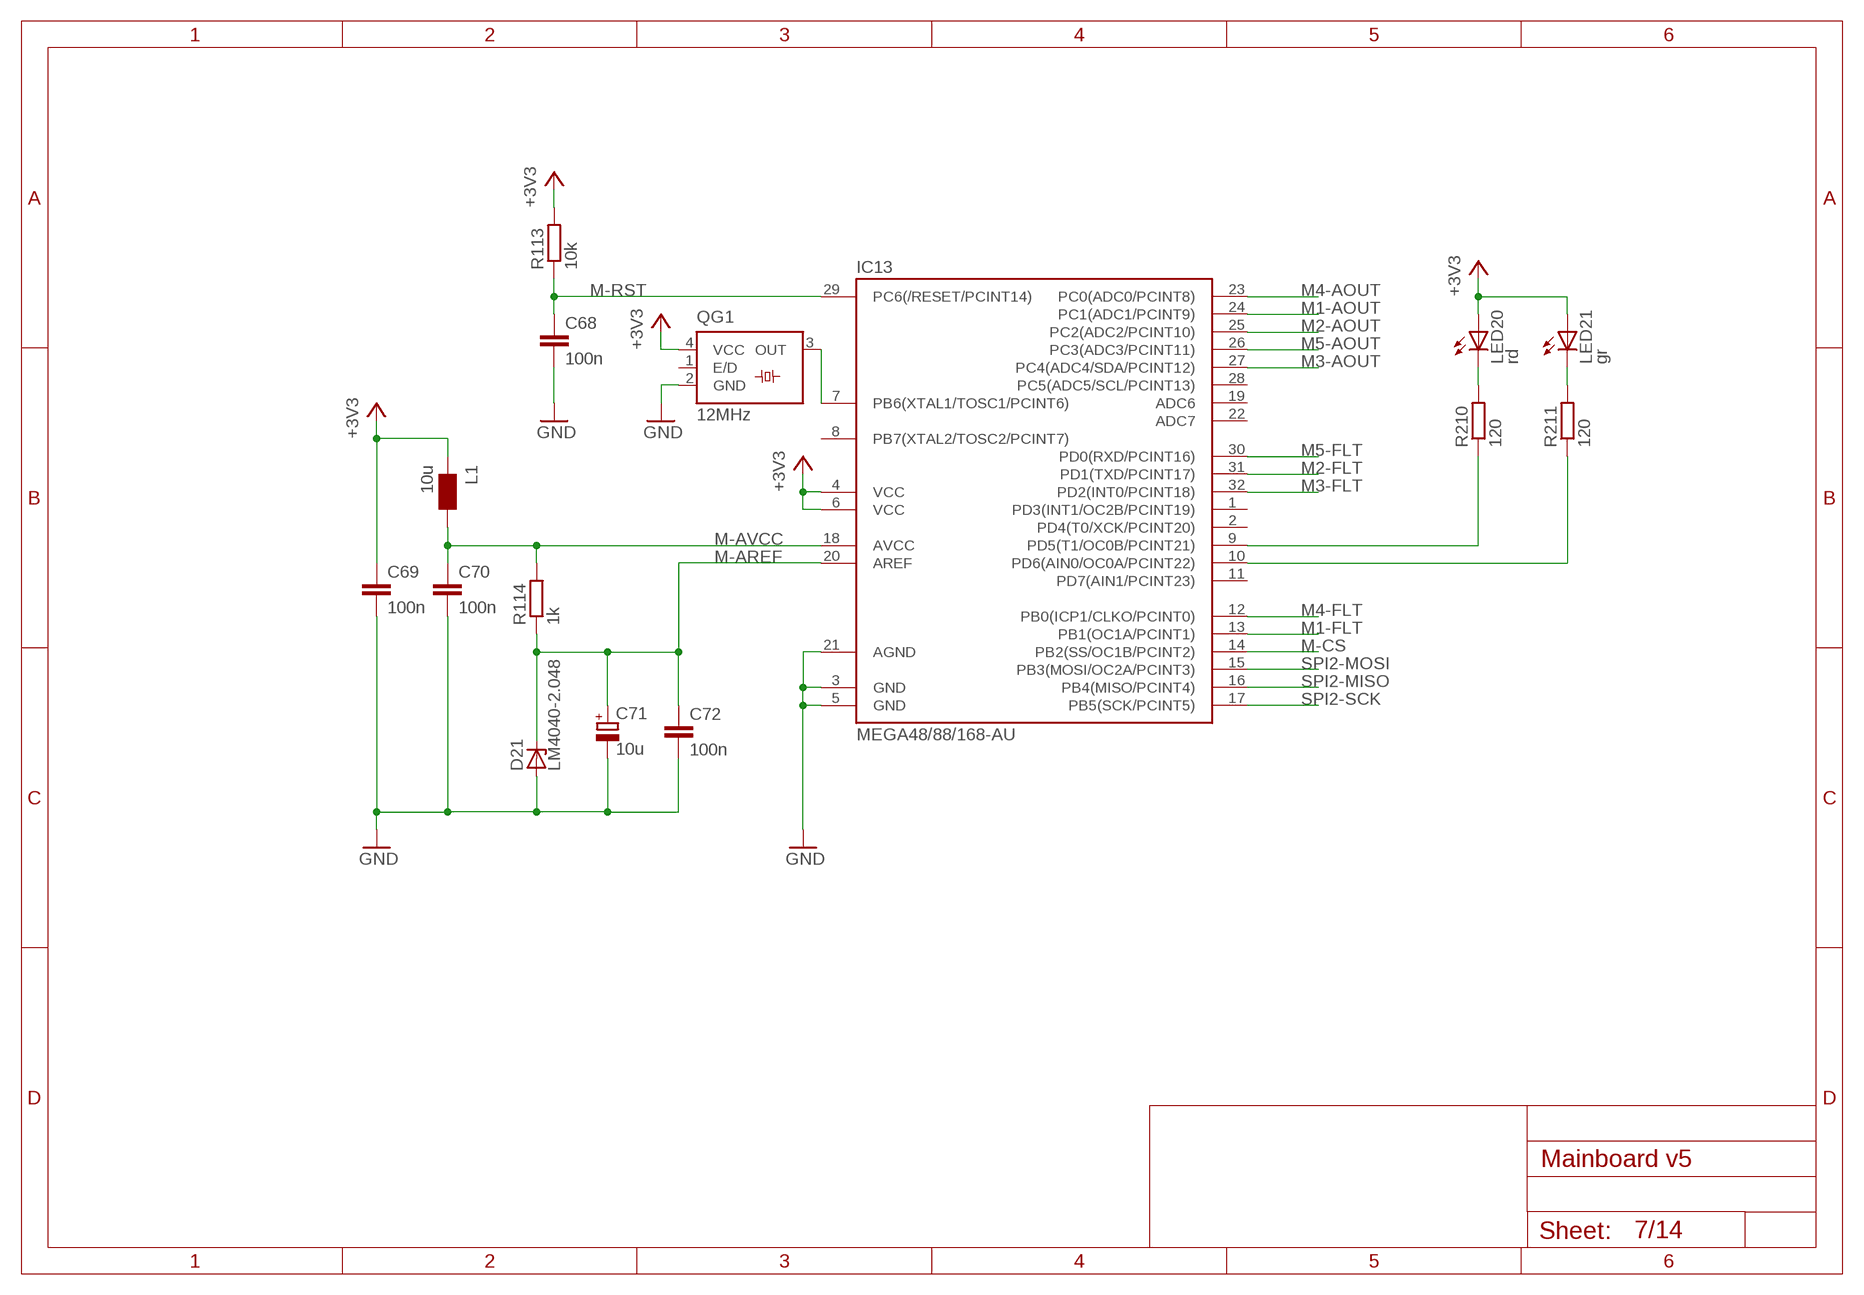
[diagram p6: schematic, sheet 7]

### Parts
C68  100n  C-EUC0805  [C0805]
C69  100n  C-EUC0805  [C0805]
C70  100n  C-EUC0805  [C0805]
C71  10u  CPOL-EUC/6032-28W  [C/6032-28W]
C72  100n  C-EUC0805  [C0805]
D21  LM4040-2.048  ZENER-DIODELM4040  [SOT23]
IC13  MEGA48/88/168-AU  [TQFP32-08]
L1  10u  WE-MI_0805  [0805]
LED20  rd  LEDCHIP-LED0805  [CHIP-LED0805]
LED21  gr  LEDCHIP-LED0805  [CHIP-LED0805]
QG1  12MHz  SM77H  [SM77H]
R113  10k  R-EU_R0805  [R0805]
R114  1k  R-EU_R0805  [R0805]
R210  120  R-EU_R0805  [R0805]
R211  120  R-EU_R0805  [R0805]

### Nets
+3V3: C69.1 IC13.4(VCC) IC13.6(VCC) L1.1 LED20.A LED21.A QG1.4(VCC) R113.2 ; also sheet 2,6,8,9,10,11,12,13,14
GND: C68.2 C69.2 C70.2 C71.- C72.2 D21.2(A) IC13.3(GND) IC13.5(GND) IC13.21(AGND) QG1.2(GND) ; also sheet 1,2,3,4,5,6,8,9,10,11,12,13,14
M1-AOUT: IC13.24(PC1(ADC1/PCINT9)) ; also sheet 6
M1-FLT: IC13.13(PB1(OC1A/PCINT1)) ; also sheet 1
M2-AOUT: IC13.25(PC2(ADC2/PCINT10)) ; also sheet 6
M2-FLT: IC13.31(PD1(TXD/PCINT17)) ; also sheet 2
M3-AOUT: IC13.27(PC4(ADC4/SDA/PCINT12)) ; also sheet 6
M3-FLT: IC13.32(PD2(INT0/PCINT18)) ; also sheet 3
M4-AOUT: IC13.23(PC0(ADC0/PCINT8)) ; also sheet 6
M4-FLT: IC13.12(PB0(ICP1/CLKO/PCINT0)) ; also sheet 4
M5-AOUT: IC13.26(PC3(ADC3/PCINT11)) ; also sheet 6
M5-FLT: IC13.30(PD0(RXD/PCINT16)) ; also sheet 5
M-AREF: C71.+ C72.1 D21.1(C) IC13.20(AREF) R114.1
M-AVCC: C70.1 IC13.18(AVCC) L1.2 R114.2
M-CS: IC13.14(PB2(SS/OC1B/PCINT2)) ; also sheet 11
M-RST: C68.1 IC13.29(PC6(/RESET/PCINT14)) R113.1 ; also sheet 11
M-XTAL: IC13.7(PB6(XTAL1/TOSC1/PCINT6)) QG1.3(OUT)
N$14: LED20.C R210.2
N$21: LED21.C R211.2
N$47: IC13.9(PD5(T1/OC0B/PCINT21)) R210.1
N$50: IC13.10(PD6(AIN0/OC0A/PCINT22)) R211.1
SPI2-MISO: IC13.16(PB4(MISO/PCINT4)) ; also sheet 9,11,14
SPI2-MOSI: IC13.15(PB3(MOSI/OC2A/PCINT3)) ; also sheet 9,11,14
SPI2-SCK: IC13.17(PB5(SCK/PCINT5)) ; also sheet 9,11,14
Unconnected: IC13.1(PD3(INT1/OC2B/PCINT19)) IC13.2(PD4(T0/XCK/PCINT20)) IC13.8(PB7(XTAL2/TOSC2/PCINT7)) IC13.11(PD7(AIN1/PCINT23)) IC13.19(ADC6) IC13.22(ADC7) IC13.28(PC5(ADC5/SCL/PCINT13)) QG1.1(E/D)

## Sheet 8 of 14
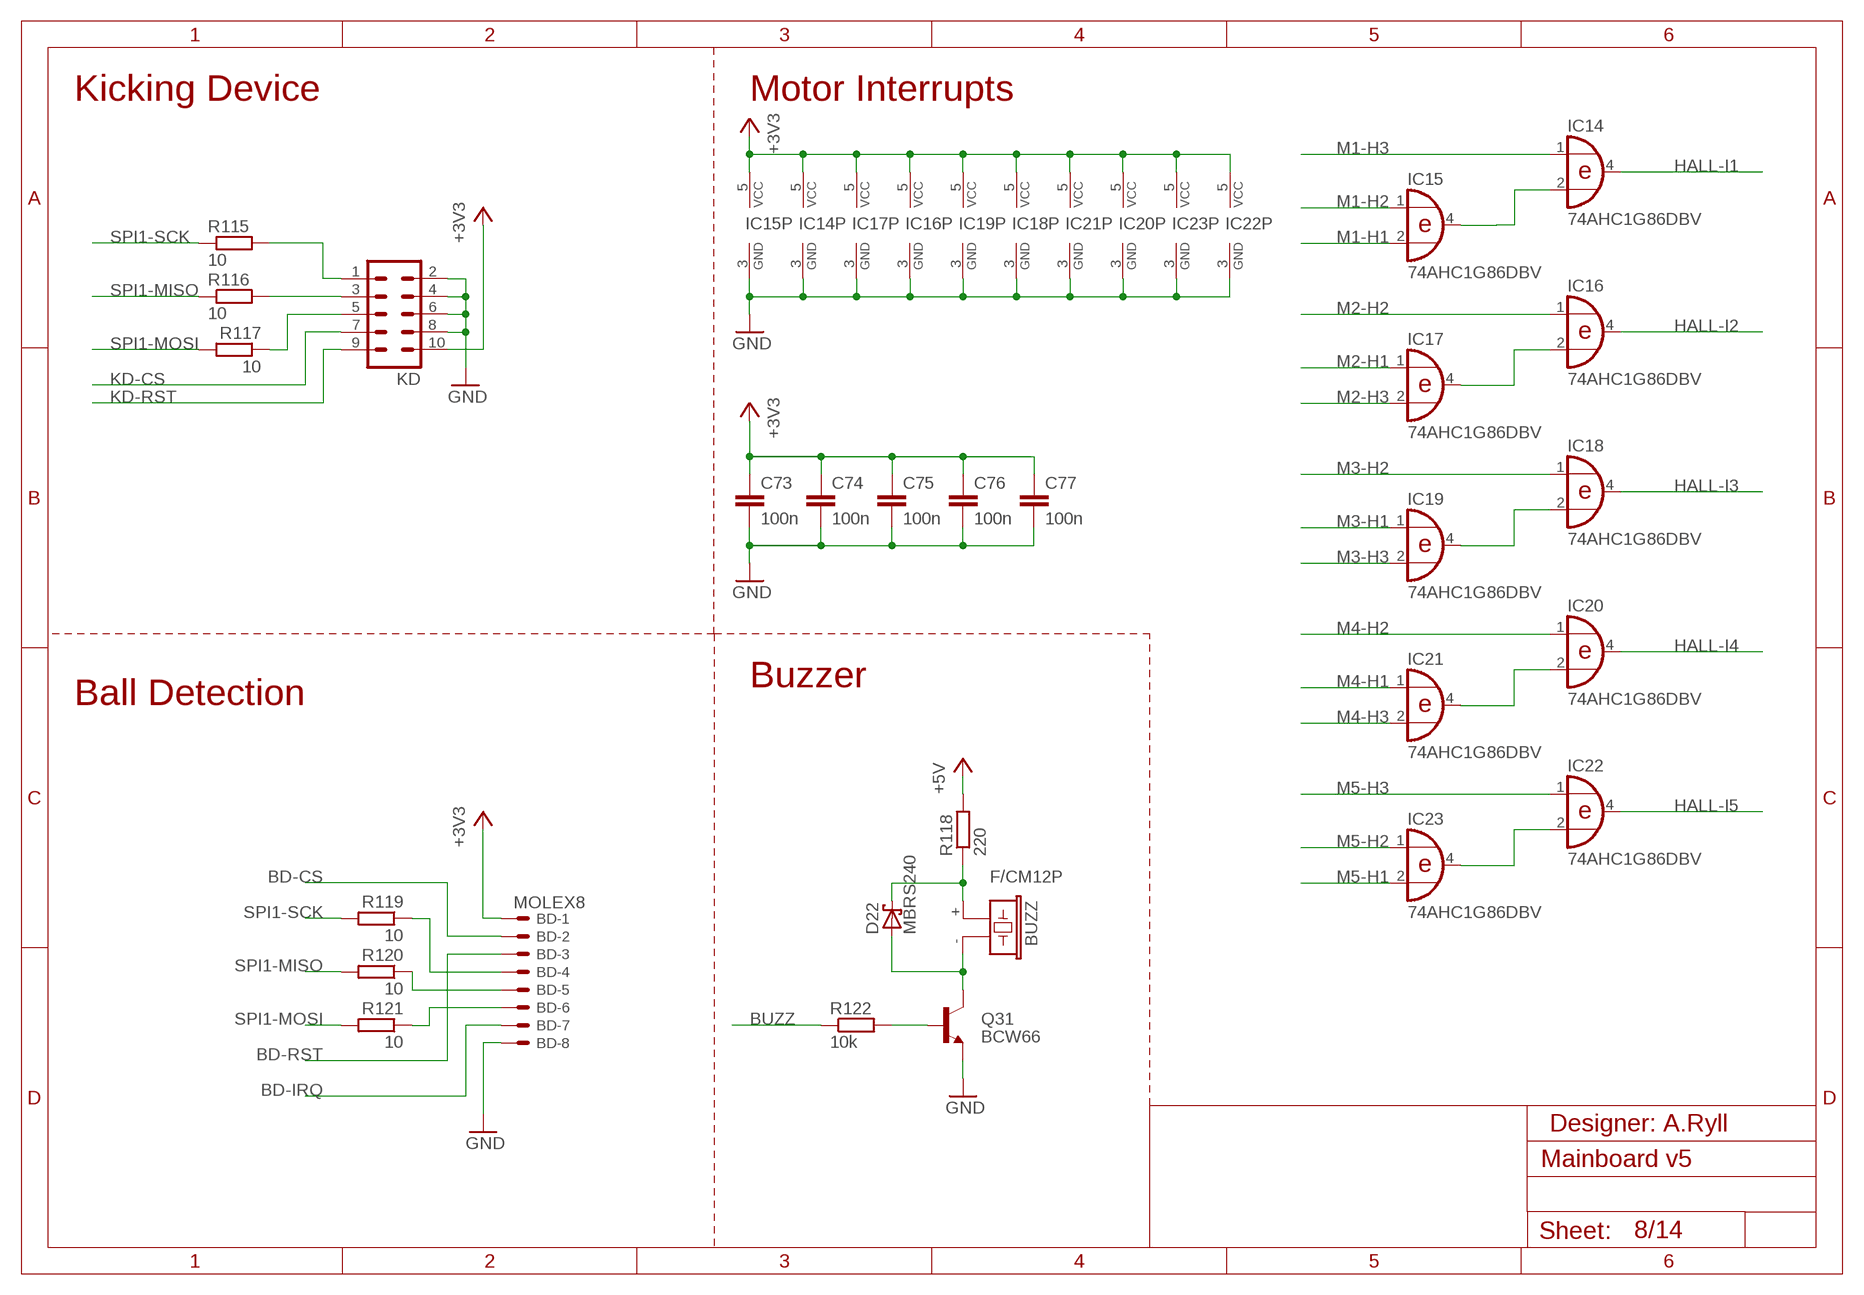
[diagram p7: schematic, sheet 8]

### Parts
BD  MOLEX8  22-27-2081-08  [6410-08]
BUZZ  F/CM12P  [F/CM12P]
C73  100n  C-EUC0805  [C0805]
C74  100n  C-EUC0805  [C0805]
C75  100n  C-EUC0805  [C0805]
C76  100n  C-EUC0805  [C0805]
C77  100n  C-EUC0805  [C0805]
D22  MBRS240  SCHOTTKY-DIODESMD  [SMB]
IC14  74AHC1G86DBV  [SOT23-5]
IC15  74AHC1G86DBV  [SOT23-5]
IC16  74AHC1G86DBV  [SOT23-5]
IC17  74AHC1G86DBV  [SOT23-5]
IC18  74AHC1G86DBV  [SOT23-5]
IC19  74AHC1G86DBV  [SOT23-5]
IC20  74AHC1G86DBV  [SOT23-5]
IC21  74AHC1G86DBV  [SOT23-5]
IC22  74AHC1G86DBV  [SOT23-5]
IC23  74AHC1G86DBV  [SOT23-5]
KD  ML10  [ML10]
Q31  BCW66  BCW60SMD  [SOT23-BEC]
R115  10  R-EU_R0805  [R0805]
R116  10  R-EU_R0805  [R0805]
R117  10  R-EU_R0805  [R0805]
R118  220  R-EU_R0805  [R0805]
R119  10  R-EU_R0805  [R0805]
R120  10  R-EU_R0805  [R0805]
R121  10  R-EU_R0805  [R0805]
R122  10k  R-EU_R0805  [R0805]

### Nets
+3V3: BD.1 C73.1 C74.1 C75.1 C76.1 C77.1 IC14.5(VCC) IC15.5(VCC) IC16.5(VCC) IC17.5(VCC) IC18.5(VCC) IC19.5(VCC) IC20.5(VCC) IC21.5(VCC) IC22.5(VCC) IC23.5(VCC) KD.10 ; also sheet 2,6,7,9,10,11,12,13,14
+5V: R118.2 ; also sheet 1,2,3,4,5,12
BD-CS: BD.2 ; also sheet 11
BD-IRQ: BD.7 ; also sheet 11
BD-RST: BD.3 ; also sheet 11
BUZZ: R122.1 ; also sheet 11
GND: BD.8 C73.2 C74.2 C75.2 C76.2 C77.2 IC14.3(GND) IC15.3(GND) IC16.3(GND) IC17.3(GND) IC18.3(GND) IC19.3(GND) IC20.3(GND) IC21.3(GND) IC22.3(GND) IC23.3(GND) KD.2 KD.4 KD.6 KD.8 Q31.E ; also sheet 1,2,3,4,5,6,7,9,10,11,12,13,14
HALL-I1: IC14.4(O) ; also sheet 11
HALL-I2: IC16.4(O) ; also sheet 11
HALL-I3: IC18.4(O) ; also sheet 11
HALL-I4: IC20.4(O) ; also sheet 11
HALL-I5: IC22.4(O) ; also sheet 11
KD-CS: KD.7 ; also sheet 11
KD-RST: KD.9 ; also sheet 11
M1-H1: IC15.2(I1) ; also sheet 1,11
M1-H2: IC15.1(I0) ; also sheet 1,11
M1-H3: IC14.1(I0) ; also sheet 1,11
M2-H1: IC17.1(I0) ; also sheet 2,11
M2-H2: IC16.1(I0) ; also sheet 2,11
M2-H3: IC17.2(I1) ; also sheet 2,11
M3-H1: IC19.1(I0) ; also sheet 3,11
M3-H2: IC18.1(I0) ; also sheet 3,11
M3-H3: IC19.2(I1) ; also sheet 3,11
M4-H1: IC21.1(I0) ; also sheet 4,11
M4-H2: IC20.1(I0) ; also sheet 4,11
M4-H3: IC21.2(I1) ; also sheet 4,11
M5-H1: IC23.2(I1) ; also sheet 5,11
M5-H2: IC23.1(I0) ; also sheet 5,11
M5-H3: IC22.1(I0) ; also sheet 5,11
N$6: BD.5 R120.1
N$15: BD.4 R119.1
N$20: BD.6 R121.1
N$22: KD.1 R115.2
N$23: KD.3 R116.2
N$24: KD.5 R117.1
N$27: BUZZ.+ D22.C R118.1
N$28: BUZZ.- D22.A Q31.C
N$29: Q31.B R122.2
N$105: IC14.2(I1) IC15.4(O)
N$106: IC16.2(I1) IC17.4(O)
N$107: IC18.2(I1) IC19.4(O)
N$108: IC20.2(I1) IC21.4(O)
N$109: IC22.2(I1) IC23.4(O)
SPI1-MISO: R116.1 R120.2 ; also sheet 9,11
SPI1-MOSI: R117.2 R121.2 ; also sheet 9,11
SPI1-SCK: R115.1 R119.2 ; also sheet 9,11

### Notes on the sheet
- Kicking Device | Motor Interrupts
- Buzzer
- Ball Detection
- Designer: A.Ryll

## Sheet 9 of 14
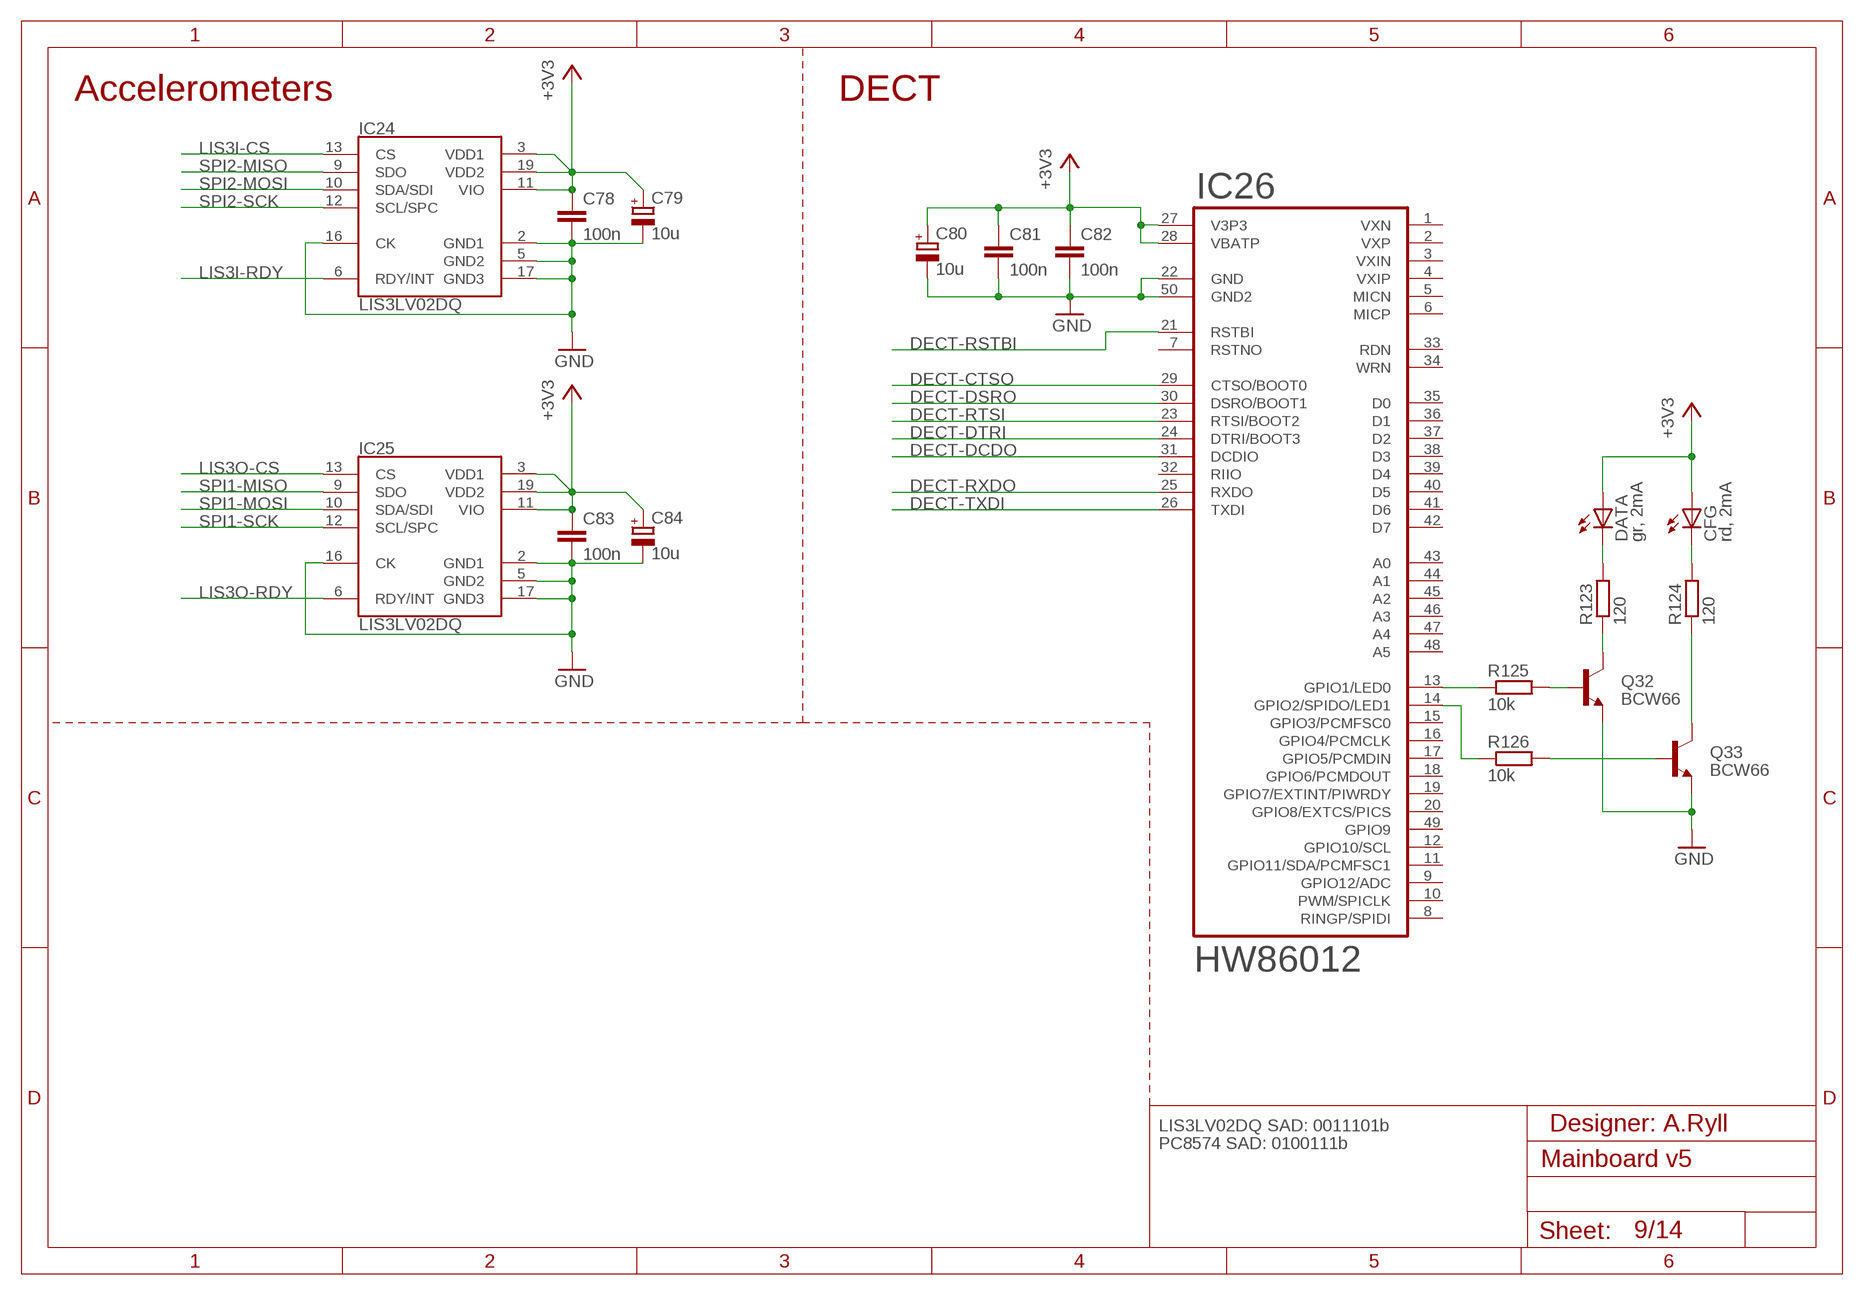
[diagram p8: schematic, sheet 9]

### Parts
C78  100n  C-EUC0805  [C0805]
C79  10u  CPOL-EUC  [PANASONIC_C]
C80  10u  CPOL-EUC  [PANASONIC_C]
C81  100n  C-EUC0805  [C0805]
C82  100n  C-EUC0805  [C0805]
C83  100n  C-EUC0805  [C0805]
C84  10u  CPOL-EUC  [PANASONIC_C]
CFG  rd, 2mA  LEDCHIP-LED0805  [CHIP-LED0805]
DATA  gr, 2mA  LEDCHIP-LED0805  [CHIP-LED0805]
IC24  LIS3LV02DQ  [QFPN-28]
IC25  LIS3LV02DQ  [QFPN-28]
IC26  HW86012  HW86012S  [PINHEAD-1.27-50]
Q32  BCW66  BCW60SMD  [SOT23-BEC]
Q33  BCW66  BCW60SMD  [SOT23-BEC]
R123  120  R-EU_R0805  [R0805]
R124  120  R-EU_R0805  [R0805]
R125  10k  R-EU_R0805  [R0805]
R126  10k  R-EU_R0805  [R0805]

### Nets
+3V3: C78.1 C79.+ C80.+ C81.1 C82.1 C83.1 C84.+ CFG.A DATA.A IC24.3(VDD1) IC24.11(VIO) IC24.19(VDD2) IC25.3(VDD1) IC25.11(VIO) IC25.19(VDD2) IC26.27(V3P3) IC26.28(VBATP) ; also sheet 2,6,7,8,10,11,12,13,14
DECT-CTSO: IC26.29(CTSO/BOOT0) ; also sheet 11
DECT-DCDO: IC26.31(DCDIO) ; also sheet 11
DECT-DSRO: IC26.30(DSRO/BOOT1) ; also sheet 11
DECT-DTRI: IC26.24(DTRI/BOOT3) ; also sheet 11
DECT-RSTBI: IC26.21(RSTBI) ; also sheet 11
DECT-RTSI: IC26.23(RTSI/BOOT2) ; also sheet 11
DECT-RXDO: IC26.25(RXDO) ; also sheet 11
DECT-TXDI: IC26.26(TXDI) ; also sheet 11
GND: C78.2 C79.- C80.- C81.2 C82.2 C83.2 C84.- IC24.2(GND1) IC24.5(GND2) IC24.16(CK) IC24.17(GND3) IC25.2(GND1) IC25.5(GND2) IC25.16(CK) IC25.17(GND3) IC26.22(GND) IC26.50(GND2) Q32.E Q33.E ; also sheet 1,2,3,4,5,6,7,8,10,11,12,13,14
LIS3I-CS: IC24.13(CS) ; also sheet 11
LIS3I-RDY: IC24.6(RDY/INT) ; also sheet 11
LIS3O-CS: IC25.13(CS) ; also sheet 11
LIS3O-RDY: IC25.6(RDY/INT) ; also sheet 11
N$101: Q33.C R124.1
N$102: Q32.C R123.1
N$113: DATA.C R123.2
N$114: CFG.C R124.2
N$193: Q32.B R125.2
N$194: Q33.B R126.2
N$195: IC26.13(GPIO1/LED0) R125.1
N$196: IC26.14(GPIO2/SPIDO/LED1) R126.1
SPI1-MISO: IC25.9(SDO) ; also sheet 8,11
SPI1-MOSI: IC25.10(SDA/SDI) ; also sheet 8,11
SPI1-SCK: IC25.12(SCL/SPC) ; also sheet 8,11
SPI2-MISO: IC24.9(SDO) ; also sheet 7,11,14
SPI2-MOSI: IC24.10(SDA/SDI) ; also sheet 7,11,14
SPI2-SCK: IC24.12(SCL/SPC) ; also sheet 7,11,14
Unconnected: IC26.1(VXN) IC26.2(VXP) IC26.3(VXIN) IC26.4(VXIP) IC26.5(MICN) IC26.6(MICP) IC26.7(RSTNO) IC26.8(RINGP/SPIDI) IC26.9(GPIO12/ADC) IC26.10(PWM/SPICLK) IC26.11(GPIO11/SDA/PCMFSC1) IC26.12(GPIO10/SCL) IC26.15(GPIO3/PCMFSC0) IC26.16(GPIO4/PCMCLK) IC26.17(GPIO5/PCMDIN) IC26.18(GPIO6/PCMDOUT) IC26.19(GPIO7/EXTINT/PIWRDY) IC26.20(GPIO8/EXTCS/PICS) IC26.32(RIIO) IC26.33(RDN) IC26.34(WRN) IC26.35(D0) IC26.36(D1) IC26.37(D2) IC26.38(D3) IC26.39(D4) IC26.40(D5) IC26.41(D6) IC26.42(D7) IC26.43(A0) IC26.44(A1) IC26.45(A2) IC26.46(A3) IC26.47(A4) IC26.48(A5) IC26.49(GPIO9)

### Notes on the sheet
- Accelerometers | DECT
- LIS3LV02DQ SAD: 0011101b | Designer: A.Ryll
- PC8574 SAD: 0100111b

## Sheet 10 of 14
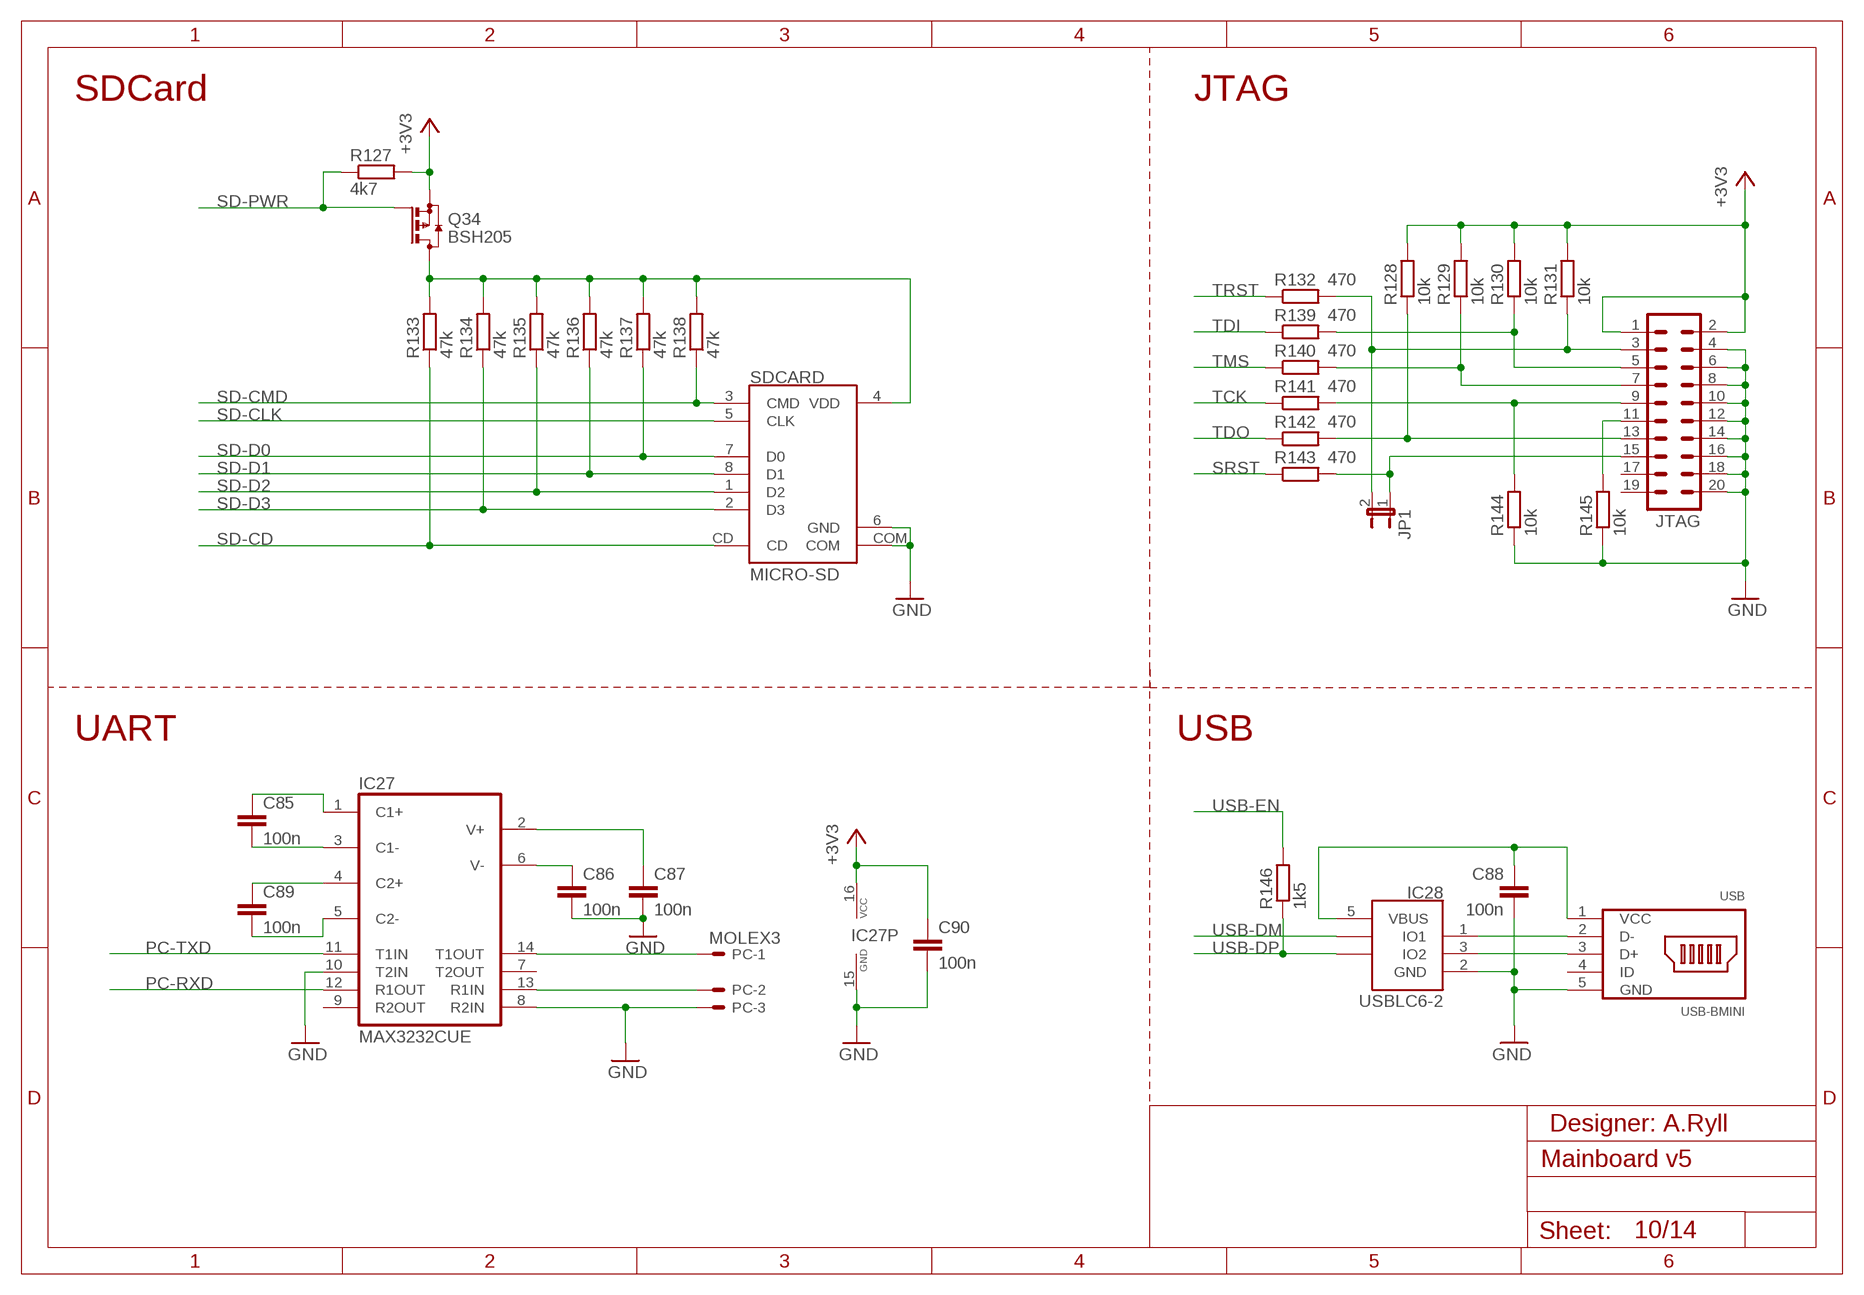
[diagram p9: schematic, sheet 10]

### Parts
C85  100n  C-EUC0805  [C0805]
C86  100n  C-EUC0805  [C0805]
C87  100n  C-EUC0805  [C0805]
C88  100n  C-EUC0805  [C0805]
C89  100n  C-EUC0805  [C0805]
C90  100n  C-EUC0805  [C0805]
IC27  MAX3232CUE  [TSSOP16]
IC28  USBLC6-2  [SOT23-6L]
JP1  JP1E  [JP1]
JTAG  ML20  [ML20]
PC  MOLEX3  22-27-2031-03  [6410-03]
Q34  BSH205  BSS84  [SOT23]
R127  4k7  R-EU_R0805  [R0805]
R128  10k  R-EU_R0805  [R0805]
R129  10k  R-EU_R0805  [R0805]
R130  10k  R-EU_R0805  [R0805]
R131  10k  R-EU_R0805  [R0805]
R132  470  R-EU_R0805  [R0805]
R133  47k  R-EU_R0805  [R0805]
R134  47k  R-EU_R0805  [R0805]
R135  47k  R-EU_R0805  [R0805]
R136  47k  R-EU_R0805  [R0805]
R137  47k  R-EU_R0805  [R0805]
R138  47k  R-EU_R0805  [R0805]
R139  470  R-EU_R0805  [R0805]
R140  470  R-EU_R0805  [R0805]
R141  470  R-EU_R0805  [R0805]
R142  470  R-EU_R0805  [R0805]
R143  470  R-EU_R0805  [R0805]
R144  10k  R-EU_R0805  [R0805]
R145  10k  R-EU_R0805  [R0805]
R146  1k5  R-EU_R0805  [R0805]
SDCARD  MICRO-SD  [MICRO-SD]
USB  USB-BMINI  [USB-BMINI]

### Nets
+3V3: C90.1 IC27.16(VCC) JTAG.1 JTAG.2 Q34.2(S) R127.2 R128.2 R129.2 R130.2 R131.2 ; also sheet 2,6,7,8,9,11,12,13,14
GND: C86.2 C87.2 C88.2 C90.2 IC27.8(R2IN) IC27.10(T2IN) IC27.15(GND) IC28.2(GND) JTAG.4 JTAG.6 JTAG.8 JTAG.10 JTAG.12 JTAG.14 JTAG.16 JTAG.18 JTAG.20 PC.3 R144.1 R145.1 SDCARD.6(GND) SDCARD.COM USB.5(GND) ; also sheet 1,2,3,4,5,6,7,8,9,11,12,13,14
JTAG-SRST: JP1.1 JTAG.15 R143.2
JTAG-TCK: JTAG.9 R141.2 R144.2
JTAG-TDI: JTAG.5 R130.1 R139.2
JTAG-TDO: JTAG.13 R128.1 R142.2
JTAG-TMS: JTAG.7 R129.1 R140.2
JTAG-TRST: JP1.2 JTAG.3 R131.1 R132.2
N$157: Q34.3(D) R133.2 R134.2 R135.2 R136.2 R137.2 R138.2 SDCARD.4(VDD)
N$173: JTAG.11 R145.2
N$176: C88.1 IC28.5(VBUS) USB.1(VCC)
N$177: IC28.1(IO1) USB.2(D-)
N$178: IC28.3(IO2) USB.3(D+)
N$179: C86.1 IC27.6(V-)
N$180: C87.1 IC27.2(V+)
N$181: IC27.14(T1OUT) PC.1
N$182: C85.2 IC27.3(C1-)
N$183: C85.1 IC27.1(C1+)
N$184: C89.1 IC27.4(C2+)
N$185: C89.2 IC27.5(C2-)
N$186: IC27.13(R1IN) PC.2
PC-RXD: IC27.12(R1OUT) ; also sheet 11
PC-TXD: IC27.11(T1IN) ; also sheet 11
SD-CD: R133.1 SDCARD.CD ; also sheet 11
SD-CLK: SDCARD.5(CLK) ; also sheet 11
SD-CMD: R138.1 SDCARD.3(CMD) ; also sheet 11
SD-D0: R137.1 SDCARD.7(D0) ; also sheet 11
SD-D1: R136.1 SDCARD.8(D1) ; also sheet 11
SD-D2: R135.1 SDCARD.1(D2) ; also sheet 11
SD-D3: R134.1 SDCARD.2(D3) ; also sheet 11
SD-PWR: Q34.1(G) R127.1 ; also sheet 11
SRST: R143.1 ; also sheet 11
TCK: R141.1 ; also sheet 11
TDI: R139.1 ; also sheet 11
TDO: R142.1 ; also sheet 11
TMS: R140.1 ; also sheet 11
TRST: R132.1 ; also sheet 11
USB-DM: IC28.6(IO1B) ; also sheet 11
USB-DP: IC28.4(IO2B) R146.1 ; also sheet 11
USB-EN: R146.2 ; also sheet 11
Unconnected: IC27.7(T2OUT) IC27.9(R2OUT) JTAG.17 JTAG.19 USB.4(ID)

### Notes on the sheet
- SDCard | JTAG
- UART | USB
- Designer: A.Ryll

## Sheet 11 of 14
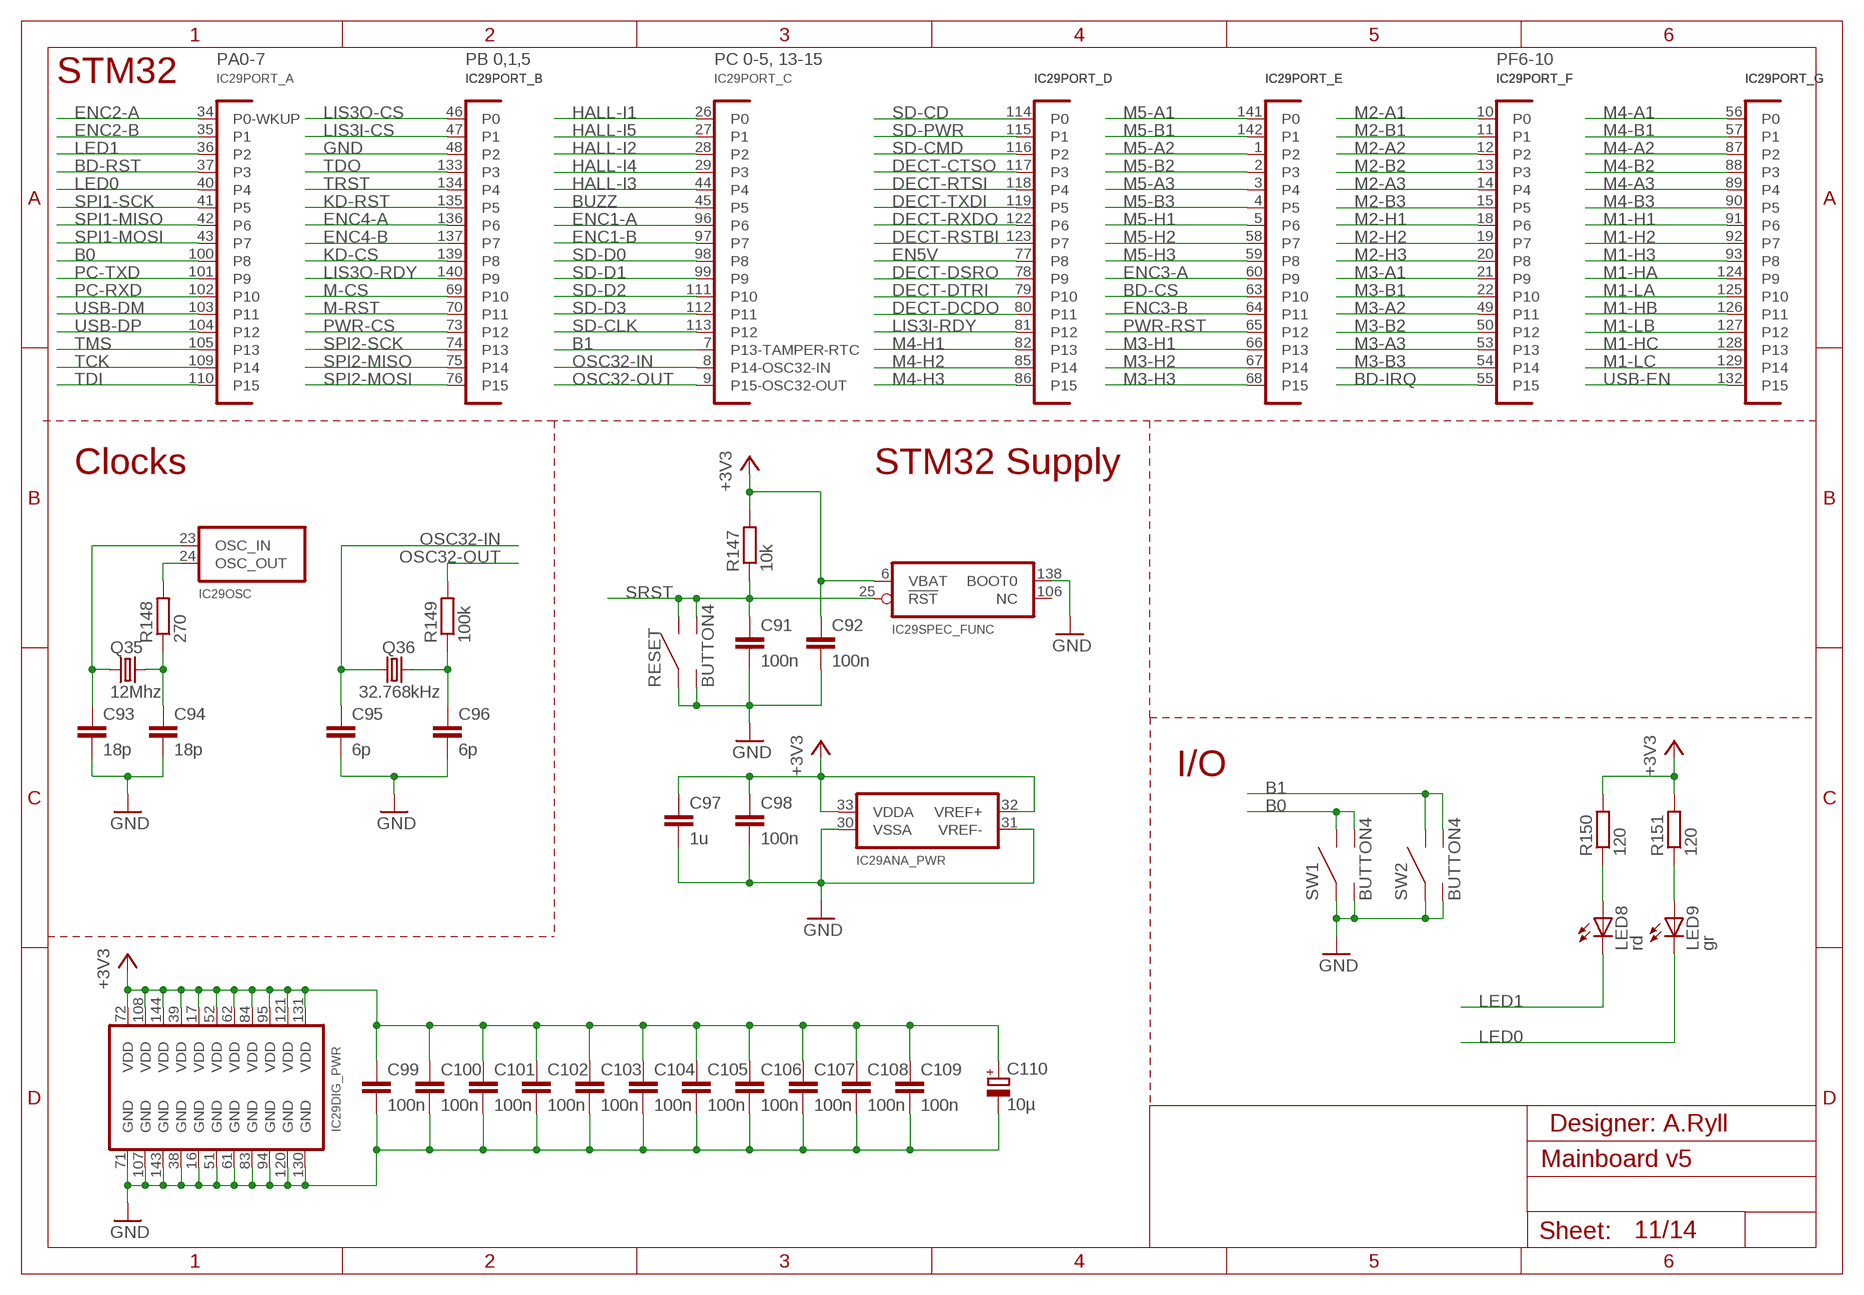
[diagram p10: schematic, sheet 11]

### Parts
C91  100n  C-EUC0805  [C0805]
C92  100n  C-EUC0805  [C0805]
C93  18p  C-EUC0805  [C0805]
C94  18p  C-EUC0805  [C0805]
C95  6p  C-EUC0805  [C0805]
C96  6p  C-EUC0805  [C0805]
C97  1u  C-EUC0805  [C0805]
C98  100n  C-EUC0805  [C0805]
C99  100n  C-EUC0805  [C0805]
C100  100n  C-EUC0805  [C0805]
C101  100n  C-EUC0805  [C0805]
C102  100n  C-EUC0805  [C0805]
C103  100n  C-EUC0805  [C0805]
C104  100n  C-EUC0805  [C0805]
C105  100n  C-EUC0805  [C0805]
C106  100n  C-EUC0805  [C0805]
C107  100n  C-EUC0805  [C0805]
C108  100n  C-EUC0805  [C0805]
C109  100n  C-EUC0805  [C0805]
C110  10µ  CPOL-EUC  [PANASONIC_C]
IC29  STM32F103ZE  [SQFP-S-20X20-144]
LED8  rd  LEDCHIP-LED0805  [CHIP-LED0805]
LED9  gr  LEDCHIP-LED0805  [CHIP-LED0805]
Q35  12Mhz  CRYSTALHC49UP  [HC49UP]
Q36  32.768kHz  CRYSTALTC26V  [TC26V]
R147  10k  R-EU_R0805  [R0805]
R148  270  R-EU_R0805  [R0805]
R149  100k  R-EU_R0805  [R0805]
R150  120  R-EU_R0805  [R0805]
R151  120  R-EU_R0805  [R0805]
RESET  BUTTON4  [BUTTON4]
SW1  BUTTON4  [BUTTON4]
SW2  BUTTON4  [BUTTON4]

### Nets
+3V3: C92.1 C97.1 C98.1 C99.1 C100.1 C101.1 C102.1 C103.1 C104.1 C105.1 C106.1 C107.1 C108.1 C109.1 C110.+ IC29.6(SPEC_FUNC:VBAT) IC29.17(DIG_PWR:VDD) IC29.32(ANA_PWR:VREF+) IC29.33(ANA_PWR:VDDA) IC29.39(DIG_PWR:VDD) IC29.52(DIG_PWR:VDD) IC29.62(DIG_PWR:VDD) IC29.72(DIG_PWR:VDD) IC29.84(DIG_PWR:VDD) IC29.95(DIG_PWR:VDD) IC29.108(DIG_PWR:VDD) IC29.121(DIG_PWR:VDD) IC29.131(DIG_PWR:VDD) IC29.144(DIG_PWR:VDD) R147.2 R150.2 R151.2 ; also sheet 2,6,7,8,9,10,12,13,14
B0: IC29.100(PORT_A:P8) SW1.3 SW1.4
B1: IC29.7(PORT_C:P13-TAMPER-RTC) SW2.3 SW2.4
BD-CS: IC29.63(PORT_E:P10) ; also sheet 8
BD-IRQ: IC29.55(PORT_F:P15) ; also sheet 8
BD-RST: IC29.37(PORT_A:P3) ; also sheet 8
BUZZ: IC29.45(PORT_C:P5) ; also sheet 8
DECT-CTSO: IC29.117(PORT_D:P3) ; also sheet 9
DECT-DCDO: IC29.80(PORT_D:P11) ; also sheet 9
DECT-DSRO: IC29.78(PORT_D:P9) ; also sheet 9
DECT-DTRI: IC29.79(PORT_D:P10) ; also sheet 9
DECT-RSTBI: IC29.123(PORT_D:P7) ; also sheet 9
DECT-RTSI: IC29.118(PORT_D:P4) ; also sheet 9
DECT-RXDO: IC29.122(PORT_D:P6) ; also sheet 9
DECT-TXDI: IC29.119(PORT_D:P5) ; also sheet 9
EN5V: IC29.77(PORT_D:P8) ; also sheet 12
ENC1-A: IC29.96(PORT_C:P6) ; also sheet 1
ENC1-B: IC29.97(PORT_C:P7) ; also sheet 1
ENC2-A: IC29.34(PORT_A:P0-WKUP) ; also sheet 2
ENC2-B: IC29.35(PORT_A:P1) ; also sheet 2
ENC3-A: IC29.60(PORT_E:P9) ; also sheet 3
ENC3-B: IC29.64(PORT_E:P11) ; also sheet 3
ENC4-A: IC29.136(PORT_B:P6) ; also sheet 4
ENC4-B: IC29.137(PORT_B:P7) ; also sheet 4
GND: C91.2 C92.2 C93.2 C94.2 C95.2 C96.2 C97.2 C98.2 C99.2 C100.2 C101.2 C102.2 C103.2 C104.2 C105.2 C106.2 C107.2 C108.2 C109.2 C110.- IC29.16(DIG_PWR:GND) IC29.30(ANA_PWR:VSSA) IC29.31(ANA_PWR:VREF-) IC29.38(DIG_PWR:GND) IC29.48(PORT_B:P2) IC29.51(DIG_PWR:GND) IC29.61(DIG_PWR:GND) IC29.71(DIG_PWR:GND) IC29.83(DIG_PWR:GND) IC29.94(DIG_PWR:GND) IC29.107(DIG_PWR:GND) IC29.120(DIG_PWR:GND) IC29.130(DIG_PWR:GND) IC29.138(SPEC_FUNC:BOOT0) IC29.143(DIG_PWR:GND) RESET.1 RESET.2 SW1.1 SW1.2 SW2.1 SW2.2 ; also sheet 1,2,3,4,5,6,7,8,9,10,12,13,14
HALL-I1: IC29.26(PORT_C:P0) ; also sheet 8
HALL-I2: IC29.28(PORT_C:P2) ; also sheet 8
HALL-I3: IC29.44(PORT_C:P4) ; also sheet 8
HALL-I4: IC29.29(PORT_C:P3) ; also sheet 8
HALL-I5: IC29.27(PORT_C:P1) ; also sheet 8
KD-CS: IC29.139(PORT_B:P8) ; also sheet 8
KD-RST: IC29.135(PORT_B:P5) ; also sheet 8
LED0: IC29.40(PORT_A:P4) LED9.C
LED1: IC29.36(PORT_A:P2) LED8.C
LIS3I-CS: IC29.47(PORT_B:P1) ; also sheet 9
LIS3I-RDY: IC29.81(PORT_D:P12) ; also sheet 9
LIS3O-CS: IC29.46(PORT_B:P0) ; also sheet 9
LIS3O-RDY: IC29.140(PORT_B:P9) ; also sheet 9
M1-H1: IC29.91(PORT_G:P6) ; also sheet 1,8
M1-H2: IC29.92(PORT_G:P7) ; also sheet 1,8
M1-H3: IC29.93(PORT_G:P8) ; also sheet 1,8
M1-HA: IC29.124(PORT_G:P9) ; also sheet 1
M1-HB: IC29.126(PORT_G:P11) ; also sheet 1
M1-HC: IC29.128(PORT_G:P13) ; also sheet 1
M1-LA: IC29.125(PORT_G:P10) ; also sheet 1
M1-LB: IC29.127(PORT_G:P12) ; also sheet 1
M1-LC: IC29.129(PORT_G:P14) ; also sheet 1
M2-A1: IC29.10(PORT_F:P0) ; also sheet 2
M2-A2: IC29.12(PORT_F:P2) ; also sheet 2
M2-A3: IC29.14(PORT_F:P4) ; also sheet 2
M2-B1: IC29.11(PORT_F:P1) ; also sheet 2
M2-B2: IC29.13(PORT_F:P3) ; also sheet 2
M2-B3: IC29.15(PORT_F:P5) ; also sheet 2
M2-H1: IC29.18(PORT_F:P6) ; also sheet 2,8
M2-H2: IC29.19(PORT_F:P7) ; also sheet 2,8
M2-H3: IC29.20(PORT_F:P8) ; also sheet 2,8
M3-A1: IC29.21(PORT_F:P9) ; also sheet 3
M3-A2: IC29.49(PORT_F:P11) ; also sheet 3
M3-A3: IC29.53(PORT_F:P13) ; also sheet 3
M3-B1: IC29.22(PORT_F:P10) ; also sheet 3
M3-B2: IC29.50(PORT_F:P12) ; also sheet 3
M3-B3: IC29.54(PORT_F:P14) ; also sheet 3
M3-H1: IC29.66(PORT_E:P13) ; also sheet 3,8
M3-H2: IC29.67(PORT_E:P14) ; also sheet 3,8
M3-H3: IC29.68(PORT_E:P15) ; also sheet 3,8
M4-A1: IC29.56(PORT_G:P0) ; also sheet 4
M4-A2: IC29.87(PORT_G:P2) ; also sheet 4
M4-A3: IC29.89(PORT_G:P4) ; also sheet 4
M4-B1: IC29.57(PORT_G:P1) ; also sheet 4
M4-B2: IC29.88(PORT_G:P3) ; also sheet 4
M4-B3: IC29.90(PORT_G:P5) ; also sheet 4
M4-H1: IC29.82(PORT_D:P13) ; also sheet 4,8
M4-H2: IC29.85(PORT_D:P14) ; also sheet 4,8
M4-H3: IC29.86(PORT_D:P15) ; also sheet 4,8
M5-A1: IC29.141(PORT_E:P0) ; also sheet 5
M5-A2: IC29.1(PORT_E:P2) ; also sheet 5
M5-A3: IC29.3(PORT_E:P4) ; also sheet 5
M5-B1: IC29.142(PORT_E:P1) ; also sheet 5
M5-B2: IC29.2(PORT_E:P3) ; also sheet 5
M5-B3: IC29.4(PORT_E:P5) ; also sheet 5
M5-H1: IC29.5(PORT_E:P6) ; also sheet 5,8
M5-H2: IC29.58(PORT_E:P7) ; also sheet 5,8
M5-H3: IC29.59(PORT_E:P8) ; also sheet 5,8
M-CS: IC29.69(PORT_B:P10) ; also sheet 7
M-RST: IC29.70(PORT_B:P11) ; also sheet 7
N$25: LED8.A R150.1
N$120: LED9.A R151.1
N$165: IC29.24(OSC:OSC_OUT) R148.2
N$168: C93.1 IC29.23(OSC:OSC_IN) Q35.1
N$169: C94.1 Q35.2 R148.1
N$171: C96.1 Q36.2 R149.1
OSC32-IN: C95.1 IC29.8(PORT_C:P14-OSC32-IN) Q36.1
OSC32-OUT: IC29.9(PORT_C:P15-OSC32-OUT) R149.2
PC-RXD: IC29.102(PORT_A:P10) ; also sheet 10
PC-TXD: IC29.101(PORT_A:P9) ; also sheet 10
PWR-CS: IC29.73(PORT_B:P12) ; also sheet 14
PWR-RST: IC29.65(PORT_E:P12) ; also sheet 14
SD-CD: IC29.114(PORT_D:P0) ; also sheet 10
SD-CLK: IC29.113(PORT_C:P12) ; also sheet 10
SD-CMD: IC29.116(PORT_D:P2) ; also sheet 10
SD-D0: IC29.98(PORT_C:P8) ; also sheet 10
SD-D1: IC29.99(PORT_C:P9) ; also sheet 10
SD-D2: IC29.111(PORT_C:P10) ; also sheet 10
SD-D3: IC29.112(PORT_C:P11) ; also sheet 10
SD-PWR: IC29.115(PORT_D:P1) ; also sheet 10
SPI1-MISO: IC29.42(PORT_A:P6) ; also sheet 8,9
SPI1-MOSI: IC29.43(PORT_A:P7) ; also sheet 8,9
SPI1-SCK: IC29.41(PORT_A:P5) ; also sheet 8,9
SPI2-MISO: IC29.75(PORT_B:P14) ; also sheet 7,9,14
SPI2-MOSI: IC29.76(PORT_B:P15) ; also sheet 7,9,14
SPI2-SCK: IC29.74(PORT_B:P13) ; also sheet 7,9,14
SRST: C91.1 IC29.25(SPEC_FUNC:!RST) R147.1 RESET.3 RESET.4 ; also sheet 10
TCK: IC29.109(PORT_A:P14) ; also sheet 10
TDI: IC29.110(PORT_A:P15) ; also sheet 10
TDO: IC29.133(PORT_B:P3) ; also sheet 10
TMS: IC29.105(PORT_A:P13) ; also sheet 10
TRST: IC29.134(PORT_B:P4) ; also sheet 10
USB-DM: IC29.103(PORT_A:P11) ; also sheet 10
USB-DP: IC29.104(PORT_A:P12) ; also sheet 10
USB-EN: IC29.132(PORT_G:P15) ; also sheet 10
Unconnected: IC29.106(SPEC_FUNC:NC)

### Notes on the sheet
- PA0-7 | PB 0,1,5 | PC 0-5, 13-15 | PF6-10
- STM32
- Clocks | STM32 Supply
- I/O
- Designer: A.Ryll

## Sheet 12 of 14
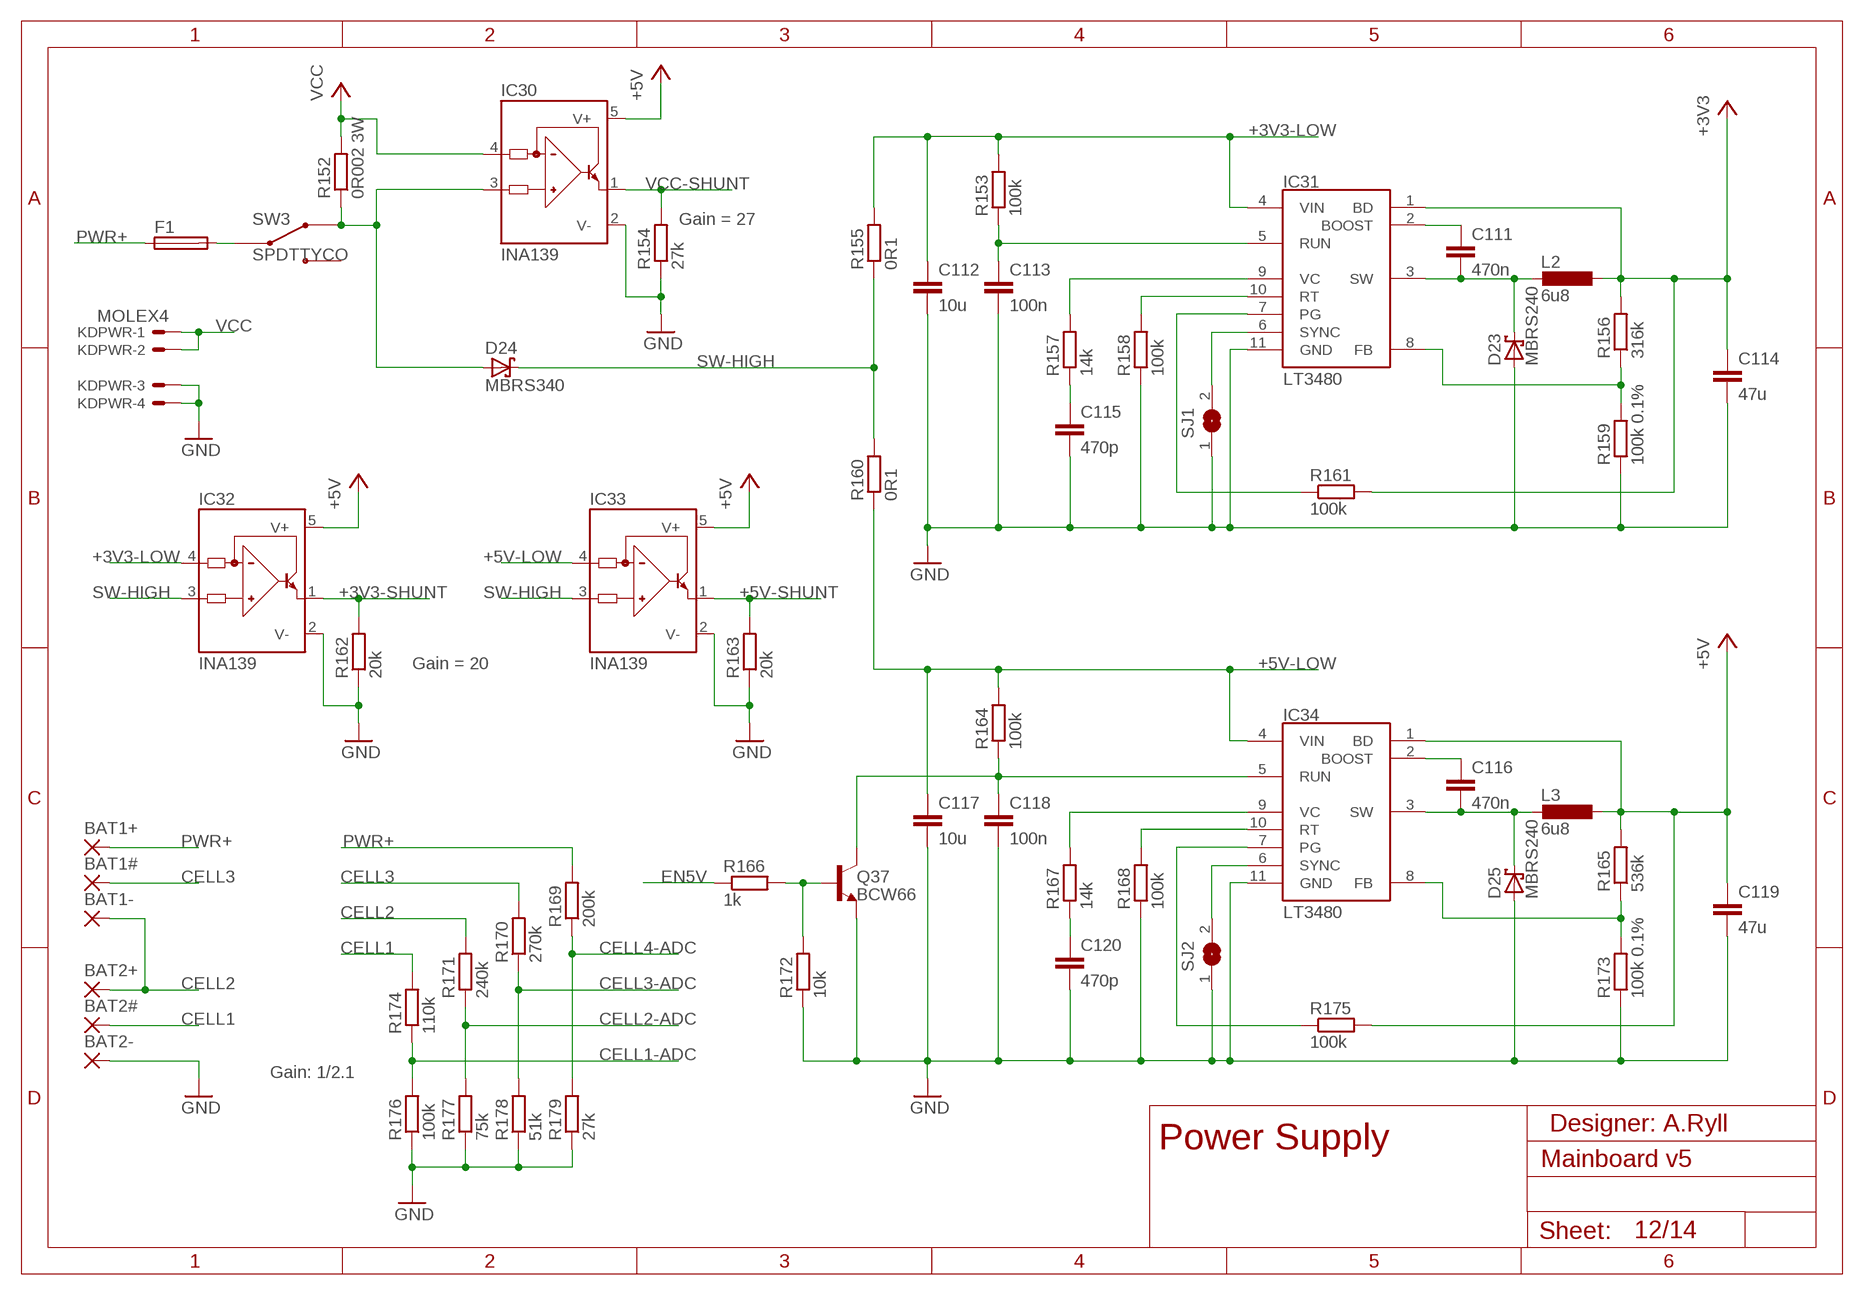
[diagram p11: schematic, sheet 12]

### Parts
BAT1#  WIREPAD2,54/1,0  [2,54/1,0]
BAT1+  WIREPAD2,54/1,5  [2,54/1,5]
BAT1-  WIREPAD2,54/1,5  [2,54/1,5]
BAT2#  WIREPAD2,54/1,0  [2,54/1,0]
BAT2+  WIREPAD2,54/1,5  [2,54/1,5]
BAT2-  WIREPAD2,54/1,5  [2,54/1,5]
C111  470n  C-EUC0805  [C0805]
C112  10u  C-EUC1210  [C1210]
C113  100n  C-EUC0805  [C0805]
C114  47u  C-EUC1210  [C1210]
C115  470p  C-EUC0805  [C0805]
C116  470n  C-EUC0805  [C0805]
C117  10u  C-EUC1210  [C1210]
C118  100n  C-EUC0805  [C0805]
C119  47u  C-EUC1210  [C1210]
C120  470p  C-EUC0805  [C0805]
D23  MBRS240  SCHOTTKY-DIODESMD  [SMB]
D24  MBRS340  SCHOTTKY-DIODESMC  [SMC]
D25  MBRS240  SCHOTTKY-DIODESMD  [SMB]
F1  FUSE5X202  [FUSE20X5-2]
IC30  INA139  INA138  [SOT23-5]
IC31  LT3480  [MSOP10]
IC32  INA139  INA138  [SOT23-5]
IC33  INA139  INA138  [SOT23-5]
IC34  LT3480  [MSOP10]
KDPWR  MOLEX4  22-27-2041-04  [6410-04]
L2  6u8  LP  [L-ELL6]
L3  6u8  LP  [L-ELL6]
Q37  BCW66  BCW60SMD  [SOT23-BEC]
R152  0R002 3W  R-EU_R2512  [R2512]
R153  100k  R-EU_R0805  [R0805]
R154  27k  R-EU_R0805  [R0805]
R155  0R1  R-EU_R2512  [R2512]
R156  316k  R-EU_R0805  [R0805]
R157  14k  R-EU_R0805  [R0805]
R158  100k  R-EU_R0805  [R0805]
R159  100k 0.1%  R-EU_R0805  [R0805]
R160  0R1  R-EU_R2512  [R2512]
R161  100k  R-EU_R0805  [R0805]
R162  20k  R-EU_R0805  [R0805]
R163  20k  R-EU_R0805  [R0805]
R164  100k  R-EU_R0805  [R0805]
R165  536k  R-EU_R0805  [R0805]
R166  1k  R-EU_R0805  [R0805]
R167  14k  R-EU_R0805  [R0805]
R168  100k  R-EU_R0805  [R0805]
R169  200k  R-EU_R0805  [R0805]
R170  270k  R-EU_R0805  [R0805]
R171  240k  R-EU_R0805  [R0805]
R172  10k  R-EU_R0805  [R0805]
R173  100k 0.1%  R-EU_R0805  [R0805]
R174  110k  R-EU_R0805  [R0805]
R175  100k  R-EU_R0805  [R0805]
R176  100k  R-EU_R0805  [R0805]
R177  75k  R-EU_R0805  [R0805]
R178  51k  R-EU_R0805  [R0805]
R179  27k  R-EU_R0805  [R0805]
SJ1  SJ  [SJ]
SJ2  SJ  [SJ]
SW3  SPDTTYCO  [TYCO-SW]

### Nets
+3V3: C114.1 IC31.1(BD) L2.P$1 R156.2 R161.2 ; also sheet 2,6,7,8,9,10,11,13,14
+3V3-LOW: C112.1 IC31.4(VIN) IC32.4(IN-) R153.2 R155.2
+3V3-SHUNT: IC32.1(OUT) R162.2 ; also sheet 13
+5V: C119.1 IC30.5(V+) IC32.5(V+) IC33.5(V+) IC34.1(BD) L3.P$1 R165.2 R175.2 ; also sheet 1,2,3,4,5,8
+5V-LOW: C117.1 IC33.4(IN-) IC34.4(VIN) R160.1 R164.2
+5V-SHUNT: IC33.1(OUT) R163.2 ; also sheet 13
CELL1: BAT2#.1(P) R174.2
CELL1-ADC: R174.1 R176.2 ; also sheet 13
CELL2: BAT1-.P$1(P) BAT2+.P$1(P) R171.2
CELL2-ADC: R171.1 R177.2 ; also sheet 13
CELL3: BAT1#.1(P) R170.2
CELL3-ADC: R170.1 R178.2 ; also sheet 13
CELL4-ADC: R169.1 R179.2 ; also sheet 13
EN: C118.1 IC34.5(RUN) Q37.C R164.1
EN5V: R166.1 ; also sheet 11
GND: BAT2-.P$1(P) C112.2 C113.2 C114.2 C115.2 C117.2 C118.2 C119.2 C120.2 D23.A D25.A IC30.2(V-) IC31.11(GND) IC32.2(V-) IC33.2(V-) IC34.11(GND) KDPWR.3 KDPWR.4 Q37.E R154.1 R158.1 R159.1 R162.1 R163.1 R168.1 R172.1 R173.1 R176.1 R177.1 R178.1 R179.1 SJ1.1 SJ2.1 ; also sheet 1,2,3,4,5,6,7,8,9,10,11,13,14
N$7: Q37.B R166.2 R172.2
N$79: IC31.6(SYNC) SJ1.2
N$82: F1.P$2 SW3.2(E)
N$115: IC34.6(SYNC) SJ2.2
N$150: C113.1 IC31.5(RUN) R153.1
N$151: IC31.9(VC) R157.2
N$174: IC31.10(RT) R158.2
N$175: C115.1 R157.1
N$187: IC31.7(PG) R161.1
N$197: C111.1 IC31.2(BOOST)
N$198: C111.2 D23.C IC31.3(SW) L2.P$2
N$200: IC31.8(FB) R156.1 R159.2
N$201: IC34.9(VC) R167.2
N$202: IC34.10(RT) R168.2
N$203: C120.1 R167.1
N$204: IC34.7(PG) R175.1
N$205: C116.1 IC34.2(BOOST)
N$206: C116.2 D25.C IC34.3(SW) L3.P$2
N$207: IC34.8(FB) R165.1 R173.2
PWR+: BAT1+.P$1(P) F1.P$1 R169.2
SW-HIGH: D24.C IC32.3(IN+) IC33.3(IN+) R155.1 R160.2
VCC: IC30.4(IN-) KDPWR.1 KDPWR.2 R152.2 ; also sheet 1,2,3,4,5
VCC-HIGH: D24.A IC30.3(IN+) R152.1 SW3.1(A1)
VCC-SHUNT: IC30.1(OUT) R154.2 ; also sheet 13
Unconnected: SW3.3(A2)

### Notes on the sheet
- Gain = 27
- Gain = 20
- Gain: 1/2.1
- Designer: A.Ryll
- Power Supply

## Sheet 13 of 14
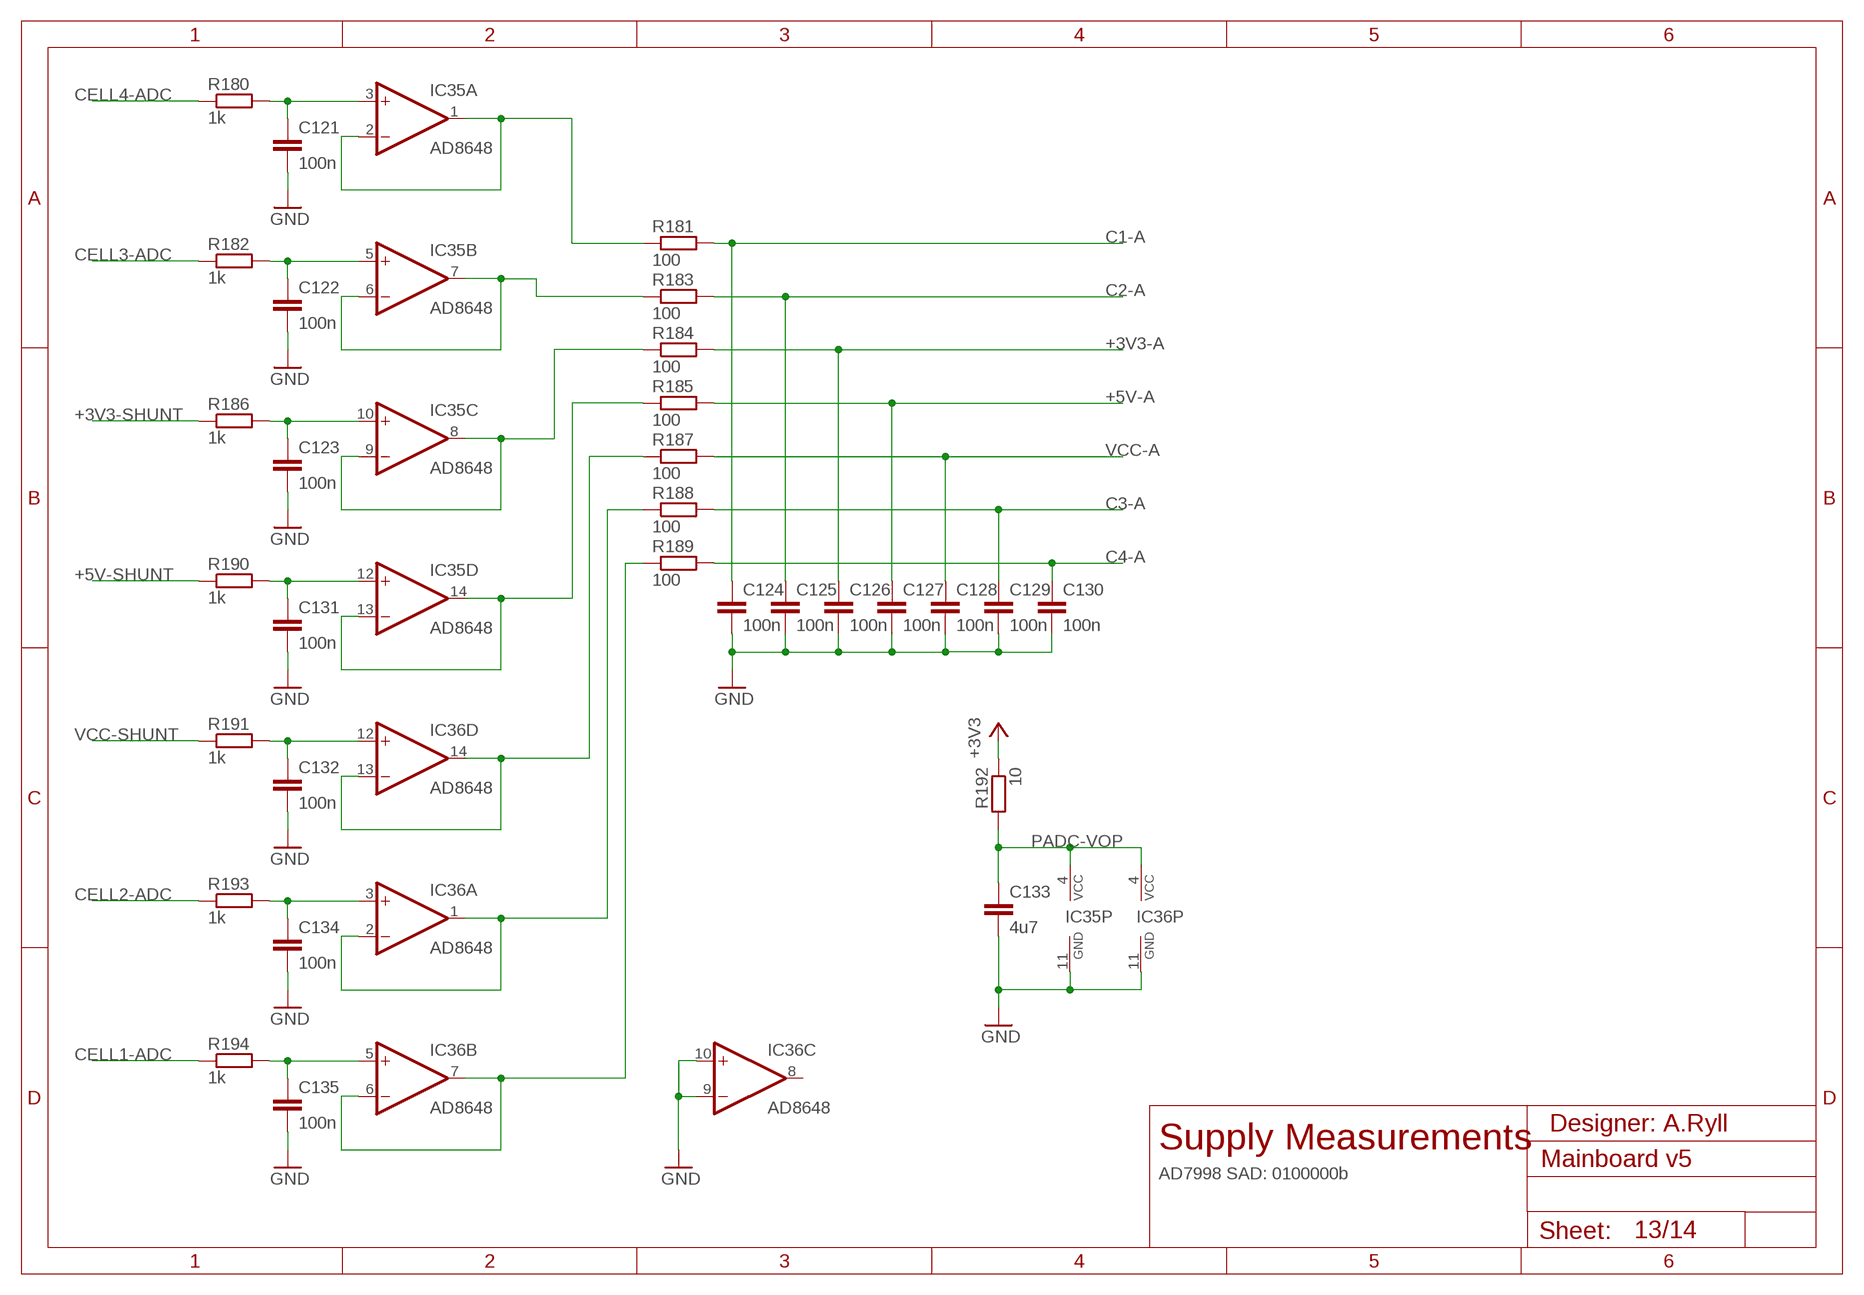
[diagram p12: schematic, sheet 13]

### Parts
C121  100n  C-EUC0805  [C0805]
C122  100n  C-EUC0805  [C0805]
C123  100n  C-EUC0805  [C0805]
C124  100n  C-EUC0805  [C0805]
C125  100n  C-EUC0805  [C0805]
C126  100n  C-EUC0805  [C0805]
C127  100n  C-EUC0805  [C0805]
C128  100n  C-EUC0805  [C0805]
C129  100n  C-EUC0805  [C0805]
C130  100n  C-EUC0805  [C0805]
C131  100n  C-EUC0805  [C0805]
C132  100n  C-EUC0805  [C0805]
C133  4u7  C-EUC0805  [C0805]
C134  100n  C-EUC0805  [C0805]
C135  100n  C-EUC0805  [C0805]
IC35  AD8648  AD-OP4  [TSSOP14]
IC36  AD8648  AD-OP4  [TSSOP14]
R180  1k  R-EU_R0805  [R0805]
R181  100  R-EU_R0805  [R0805]
R182  1k  R-EU_R0805  [R0805]
R183  100  R-EU_R0805  [R0805]
R184  100  R-EU_R0805  [R0805]
R185  100  R-EU_R0805  [R0805]
R186  1k  R-EU_R0805  [R0805]
R187  100  R-EU_R0805  [R0805]
R188  100  R-EU_R0805  [R0805]
R189  100  R-EU_R0805  [R0805]
R190  1k  R-EU_R0805  [R0805]
R191  1k  R-EU_R0805  [R0805]
R192  10  R-EU_R0805  [R0805]
R193  1k  R-EU_R0805  [R0805]
R194  1k  R-EU_R0805  [R0805]

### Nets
+3V3: R192.1 ; also sheet 2,6,7,8,9,10,11,12,14
+3V3-A: C126.1 R184.2 ; also sheet 14
+3V3-SHUNT: R186.1 ; also sheet 12
+5V-A: C127.1 R185.2 ; also sheet 14
+5V-SHUNT: R190.1 ; also sheet 12
C1-A: C124.1 R181.2 ; also sheet 14
C2-A: C125.1 R183.2 ; also sheet 14
C3-A: C129.1 R188.2 ; also sheet 14
C4-A: C130.1 R189.2 ; also sheet 14
CELL1-ADC: R194.1 ; also sheet 12
CELL2-ADC: R193.1 ; also sheet 12
CELL3-ADC: R182.1 ; also sheet 12
CELL4-ADC: R180.1 ; also sheet 12
GND: C121.2 C122.2 C123.2 C124.2 C125.2 C126.2 C127.2 C128.2 C129.2 C130.2 C131.2 C132.2 C133.2 C134.2 C135.2 IC35.11(P:GND) IC36.9(C:-IN) IC36.10(C:+IN) IC36.11(P:GND) ; also sheet 1,2,3,4,5,6,7,8,9,10,11,12,14
N$78: C121.1 IC35.3(A:+IN) R180.2
N$84: C132.1 IC36.12(D:+IN) R191.2
N$85: IC36.13(D:-IN) IC36.14(D:OUT) R187.1
N$87: C134.1 IC36.3(A:+IN) R193.2
N$88: IC36.1(A:OUT) IC36.2(A:-IN) R188.1
N$90: C135.1 IC36.5(B:+IN) R194.2
N$91: IC36.6(B:-IN) IC36.7(B:OUT) R189.1
N$116: IC35.1(A:OUT) IC35.2(A:-IN) R181.1
N$118: C122.1 IC35.5(B:+IN) R182.2
N$119: IC35.6(B:-IN) IC35.7(B:OUT) R183.1
N$122: C123.1 IC35.10(C:+IN) R186.2
N$123: IC35.8(C:OUT) IC35.9(C:-IN) R184.1
N$125: C131.1 IC35.12(D:+IN) R190.2
N$126: IC35.13(D:-IN) IC35.14(D:OUT) R185.1
PADC-VOP: C133.1 IC35.4(P:VCC) IC36.4(P:VCC) R192.2
VCC-A: C128.1 R187.2 ; also sheet 14
VCC-SHUNT: R191.1 ; also sheet 12
Unconnected: IC36.8(C:OUT)

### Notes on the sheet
- Designer: A.Ryll
- Supply Measurements
- AD7998 SAD: 0100000b

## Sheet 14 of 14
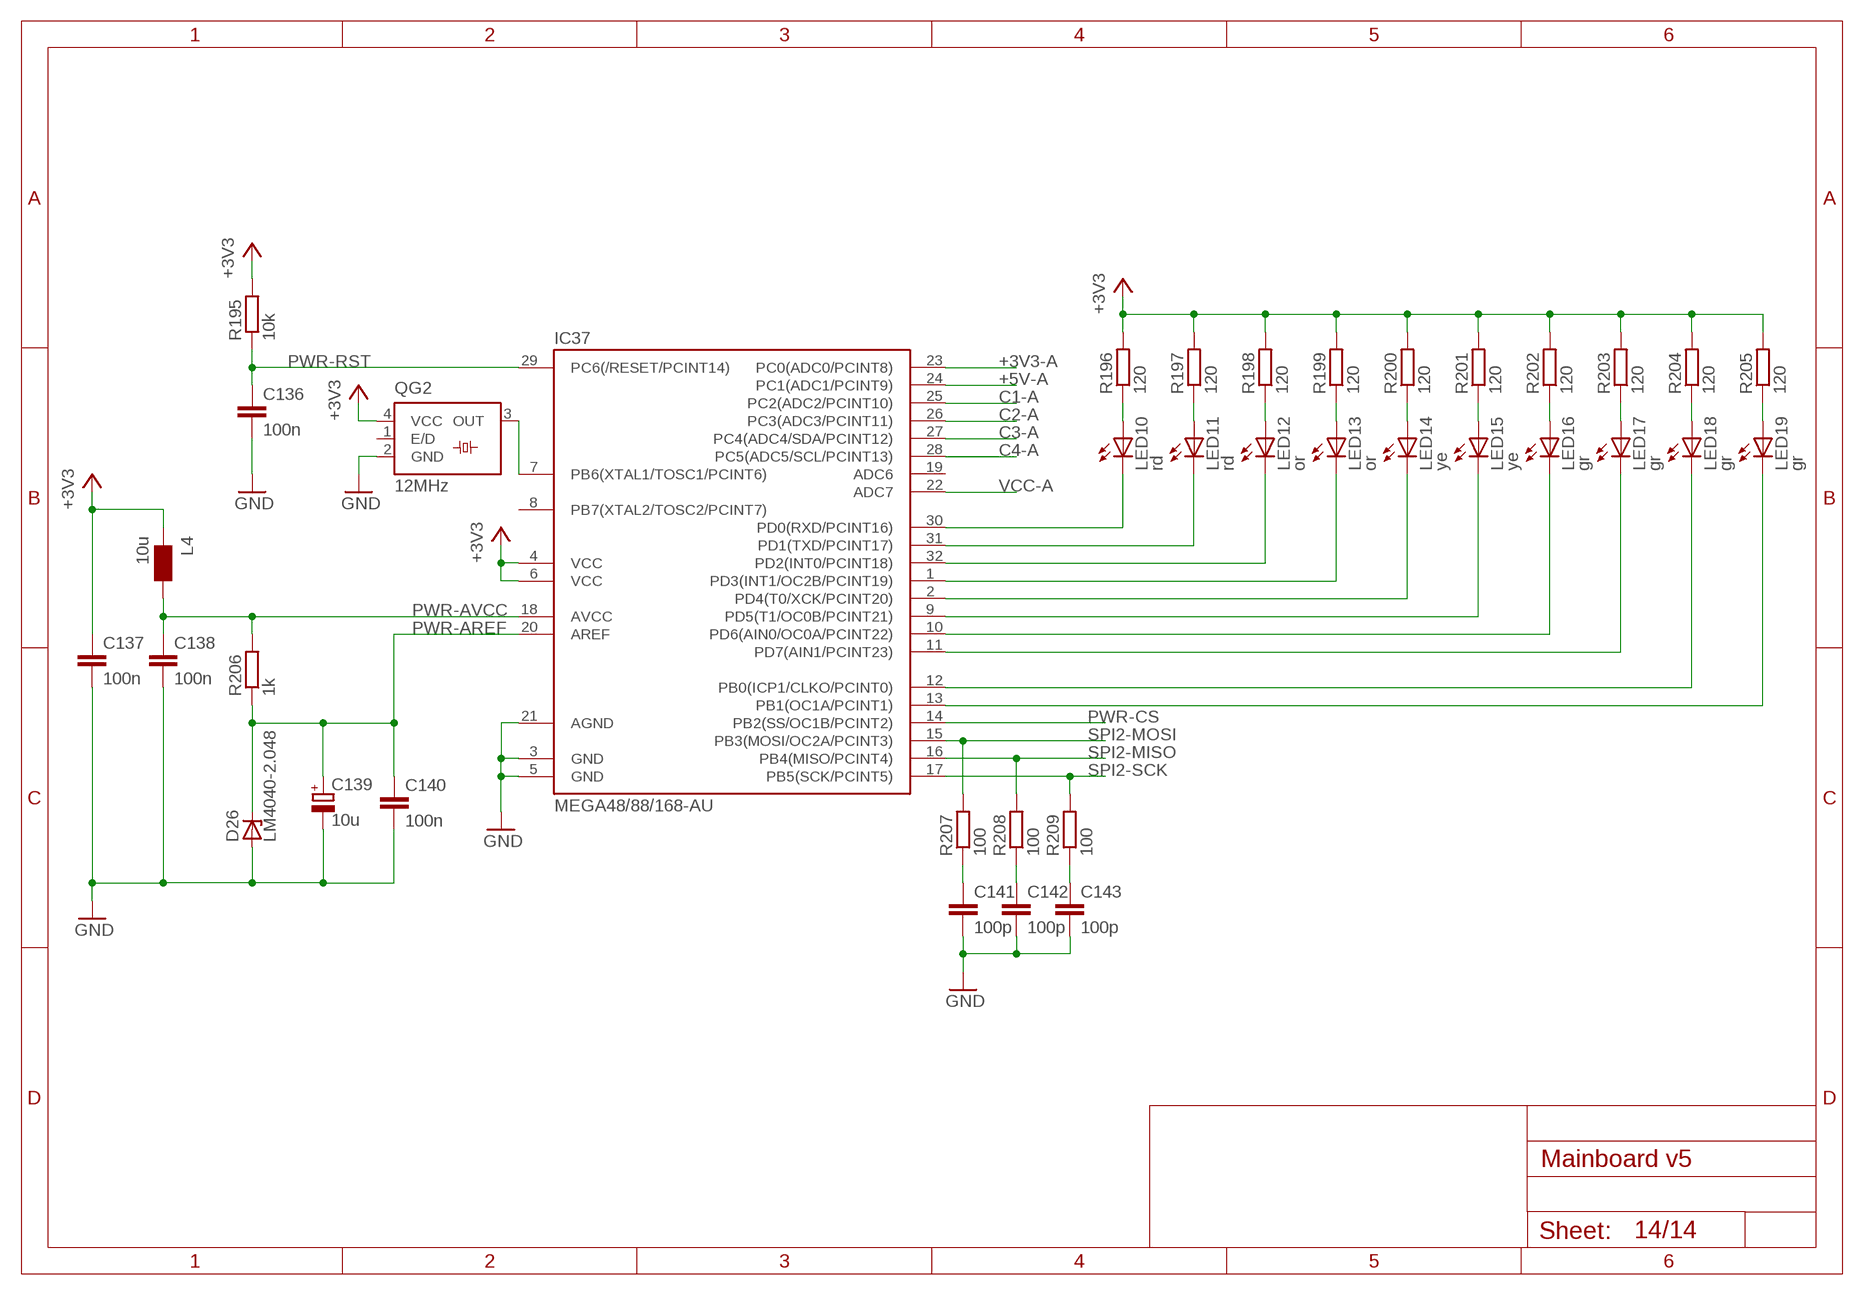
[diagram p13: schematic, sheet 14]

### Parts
C136  100n  C-EUC0805  [C0805]
C137  100n  C-EUC0805  [C0805]
C138  100n  C-EUC0805  [C0805]
C139  10u  CPOL-EUC/6032-28W  [C/6032-28W]
C140  100n  C-EUC0805  [C0805]
C141  100p  C-EUC0805  [C0805]
C142  100p  C-EUC0805  [C0805]
C143  100p  C-EUC0805  [C0805]
D26  LM4040-2.048  ZENER-DIODELM4040  [SOT23]
IC37  MEGA48/88/168-AU  [TQFP32-08]
L4  10u  WE-MI_0805  [0805]
LED10  rd  LEDCHIP-LED0805  [CHIP-LED0805]
LED11  rd  LEDCHIP-LED0805  [CHIP-LED0805]
LED12  or  LEDCHIP-LED0805  [CHIP-LED0805]
LED13  or  LEDCHIP-LED0805  [CHIP-LED0805]
LED14  ye  LEDCHIP-LED0805  [CHIP-LED0805]
LED15  ye  LEDCHIP-LED0805  [CHIP-LED0805]
LED16  gr  LEDCHIP-LED0805  [CHIP-LED0805]
LED17  gr  LEDCHIP-LED0805  [CHIP-LED0805]
LED18  gr  LEDCHIP-LED0805  [CHIP-LED0805]
LED19  gr  LEDCHIP-LED0805  [CHIP-LED0805]
QG2  12MHz  SM77H  [SM77H]
R195  10k  R-EU_R0805  [R0805]
R196  120  R-EU_R0805  [R0805]
R197  120  R-EU_R0805  [R0805]
R198  120  R-EU_R0805  [R0805]
R199  120  R-EU_R0805  [R0805]
R200  120  R-EU_R0805  [R0805]
R201  120  R-EU_R0805  [R0805]
R202  120  R-EU_R0805  [R0805]
R203  120  R-EU_R0805  [R0805]
R204  120  R-EU_R0805  [R0805]
R205  120  R-EU_R0805  [R0805]
R206  1k  R-EU_R0805  [R0805]
R207  100  R-EU_R0805  [R0805]
R208  100  R-EU_R0805  [R0805]
R209  100  R-EU_R0805  [R0805]

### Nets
+3V3: C137.1 IC37.4(VCC) IC37.6(VCC) L4.1 QG2.4(VCC) R195.2 R196.2 R197.2 R198.2 R199.2 R200.2 R201.2 R202.2 R203.2 R204.2 R205.2 ; also sheet 2,6,7,8,9,10,11,12,13
+3V3-A: IC37.23(PC0(ADC0/PCINT8)) ; also sheet 13
+5V-A: IC37.24(PC1(ADC1/PCINT9)) ; also sheet 13
C1-A: IC37.25(PC2(ADC2/PCINT10)) ; also sheet 13
C2-A: IC37.26(PC3(ADC3/PCINT11)) ; also sheet 13
C3-A: IC37.27(PC4(ADC4/SDA/PCINT12)) ; also sheet 13
C4-A: IC37.28(PC5(ADC5/SCL/PCINT13)) ; also sheet 13
GND: C136.2 C137.2 C138.2 C139.- C140.2 C141.2 C142.2 C143.2 D26.2(A) IC37.3(GND) IC37.5(GND) IC37.21(AGND) QG2.2(GND) ; also sheet 1,2,3,4,5,6,7,8,9,10,11,12,13
N$26: LED10.A R196.1
N$30: LED11.A R197.1
N$31: LED12.A R198.1
N$32: LED13.A R199.1
N$94: LED14.A R200.1
N$98: LED15.A R201.1
N$103: LED16.A R202.1
N$104: LED17.A R203.1
N$110: LED18.A R204.1
N$111: LED19.A R205.1
N$112: IC37.30(PD0(RXD/PCINT16)) LED10.C
N$149: IC37.31(PD1(TXD/PCINT17)) LED11.C
N$152: IC37.32(PD2(INT0/PCINT18)) LED12.C
N$153: IC37.1(PD3(INT1/OC2B/PCINT19)) LED13.C
N$156: IC37.2(PD4(T0/XCK/PCINT20)) LED14.C
N$159: IC37.9(PD5(T1/OC0B/PCINT21)) LED15.C
N$160: IC37.10(PD6(AIN0/OC0A/PCINT22)) LED16.C
N$161: IC37.11(PD7(AIN1/PCINT23)) LED17.C
N$164: IC37.12(PB0(ICP1/CLKO/PCINT0)) LED18.C
N$166: IC37.13(PB1(OC1A/PCINT1)) LED19.C
N$167: C141.1 R207.1
N$170: C142.1 R208.1
N$172: C143.1 R209.1
PWR-AREF: C139.+ C140.1 D26.1(C) IC37.20(AREF) R206.1
PWR-AVCC: C138.1 IC37.18(AVCC) L4.2 R206.2
PWR-CS: IC37.14(PB2(SS/OC1B/PCINT2)) ; also sheet 11
PWR-RST: C136.1 IC37.29(PC6(/RESET/PCINT14)) R195.1 ; also sheet 11
PWR-XTAL: IC37.7(PB6(XTAL1/TOSC1/PCINT6)) QG2.3(OUT)
SPI2-MISO: IC37.16(PB4(MISO/PCINT4)) R208.2 ; also sheet 7,9,11
SPI2-MOSI: IC37.15(PB3(MOSI/OC2A/PCINT3)) R207.2 ; also sheet 7,9,11
SPI2-SCK: IC37.17(PB5(SCK/PCINT5)) R209.2 ; also sheet 7,9,11
VCC-A: IC37.22(ADC7) ; also sheet 13
Unconnected: IC37.8(PB7(XTAL2/TOSC2/PCINT7)) IC37.19(ADC6) QG2.1(E/D)

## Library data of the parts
BAT1# BAT1+ BAT1- BAT2# BAT2+ BAT2- = Marvin:WIREPAD: Wire PAD connect wire on PCB
BD M5 = con-molex:22-?-08: CONNECTOR wire to board 2.54 mm (.1 inch) pitch header
BUZZ = buzzer:F/CM12P: BUZZER
C1 C12 C24 C35 C46 = Marvin:CPOL-EU
C2-C11 C13-C23 C25-C34 C36-C45 C47-C70 C72-C78 C81-C83 C85-C109 C111-C138 C140-C143 = rcl:C-EU: CAPACITOR, European symbol
C71 C79 C80 C84 C110 C139 = rcl:CPOL-EU: POLARIZED CAPACITOR, European symbol
CFG DATA FLT1-FLT5 LED8-LED21 = led:LED: LED
D1-D20 = diode:DIODE-: DIODE
D21 D26 = Marvin:ZENER-DIODE: Z-Diode
D22-D25 = diode:SCHOTTKY-DIODE: Schottky Diode
ENC1-ENC4 KDPWR = con-molex:22-?-04: CONNECTOR wire to board 2.54 mm (.1 inch) pitch header
F1 = Marvin:FUSE5X20: 1 SCHURTER 0031.3558
IC1 IC2 IC5-IC7 = Marvin:IR2130
IC3 IC4 = 74xx-little-de:74*1G08: 2-input AND gate
IC8-IC12 = Marvin:AD-OP1
IC13 IC37 = avr-6:MEGA48/88/168
IC14-IC23 = 74xx-little-de:74*1G86: 2-input EXCLUSIV-OR gate
IC24 IC25 = Marvin:LIS3LV02DQ
IC26 = Marvin:HW86012
IC27 = maxim:MAX3232*: True RS-232 Transceivers 3.0V to 5.5V, Low-Power up to 1Mbps, Using Four 0.1µF External Capacitors Source: http://pdfserv.maxim-ic.com/en/ds/MAX3222-MAX3241.pdf
IC28 = Marvin:USBLC6-2
IC29 = Marvin:STM32F103ZE: 72 MHz, 64KB RAM, 512 KB Flash
IC30 IC32 IC33 = burr-brown:INA138: High-Side Measurement Current Shunt Monitor
IC31 IC34 = Marvin:LT3480
IC35 IC36 = Marvin:AD-OP4
JP1 = jumper:JP1E: JUMPER
JTAG = con-harting-ml:ML20: HARTING
KD = con-harting-ml:ML10: HARTING
L1 L4 = wuerth-elektronik:WE-MI: SMD Multilayer Inductor WE-MI
L2 L3 = Marvin:L
M1-M4 = Marvin:MOLEX11
PC = con-molex:22-?-03: CONNECTOR wire to board 2.54 mm (.1 inch) pitch header
Q1-Q30 = Marvin:NMOS4D
Q31-Q33 Q37 = transistor-npn:BCW60*: NPN Transistor
Q34 = transistor-small-signal:BSS84: P-CHANNEL MOS FET
Q35 Q36 = crystal:CRYSTAL: CRYSTAL
QG1 QG2 = Marvin:SM77H: 3.3V CMOS Clock Oscillator Source: www.pletronics.com .. sm77h%203.3v.pdf
R1-R211 = rcl:R-EU_: RESISTOR, European symbol
RESET SW1 SW2 = Marvin:BUTTON4: Tyco Push Button FSM2JSMA Farnell Order: 3801287
SDCARD = Marvin:MICRO-SD
SJ1 SJ2 = jumper:SJ: SMD solder JUMPER
SW3 = Marvin:SPDT: Tyco Number: AE101J1AQ404
USB = Marvin:USB-BMINI

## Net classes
0 default: width 0.152 mm, clearance 0.152 mm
